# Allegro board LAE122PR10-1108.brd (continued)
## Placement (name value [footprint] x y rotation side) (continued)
RV14  -  [R_0402]  18.77 86.05 180 top
RV15  -  [R_0402]  18.77 86.94 180 top
RV16  -  [R_0402]  18.77 84.21 180 top
RV17  -  [R_0402]  18.77 85.1 180 top
RV18  -  [R_0402]  18.49 77.04 0 top
RV19  -  [R_0402]  20.46 91.39 0 bottom
RV20  -  [R_0402]  23.6 91.39 180 bottom
RV21  -  [R_0402]  24.03 88.67 270 bottom
RV22  -  [R_0402]  16.79 89.85 90 top
RV23  -  [R_0402]  16.79 88.99 270 top
RV26  -  [R_0402]  16.72 81.43 270 bottom
RV29  -  [R_0402]  16.72 83.27 270 bottom
RV32  -  [R_0402]  16.72 86.96 270 bottom
RV35  -  [R_0402]  16.72 85.11 270 bottom
RV70  -  [R_0402]  106.2 131.25 90 top
RV71  -  [R_0402]  107.08 129.31 270 top
RV73  -  [R_0402]  110.5 132.22 0 top
RV74  -  [R_0402]  113.26 132.22 180 top
RV76  -  [R_0402]  107.08 131.25 90 top
RV77  -  [R_0402]  106.2 129.31 270 top
RV79  -  [R_0402]  119.34 131.82 90 bottom
RV80  -  [R_0402]  120.23 131.82 90 bottom
RV81  -  [R_0402]  122.01 131.82 90 bottom
RV82  -  [R_0402]  121.12 131.82 90 bottom
RV83  -  [R_0402]  122.9 131.82 90 bottom
RV84  -  [R_0402]  123.79 131.82 90 bottom
RV85  -  [R_0402]  119.33 128.22 0 bottom
RV87  -  [R_0402]  114.57 126.88 0 top
RV88  -  [R_0402]  114.57 127.77 0 top
RV89  -  [R_0402]  108.35 125.69 270 bottom
RV90  -  [R_0402]  119.33 130.19 0 bottom
RV91  -  [R_0402]  119.33 129.3 0 bottom
RV93  -  [R_0402]  119.33 126.44 0 bottom
RV94  -  [R_0402]  119.33 125.55 0 bottom
RV95  -  [R_0402]  119.33 127.33 0 bottom
RV97  -  [R_0402]  107.28 126.33 270 bottom
RZ8  -  [R_0402]  233.32 55.21 270 top
RZ9  -  [R_0402]  233.32 52.51 90 top
RZ10  -  [R_0402]  222.53 58.57 270 top
RZ18  -  [R_0402]  209.5 58.49 0 top
RZ19  -  [R_0402]  212.19 58.49 180 top
RZ20  -  [R_0402]  214.07 54.94 0 top
RZ21  -  [R_0402]  216.76 54.94 180 top
RZ22  -  [R_0402]  210.46 57.11 270 top
RZ23  -  [R_0402]  211.35 57.11 270 top
RZ25  -  [R_0402]  285.66 12.58 180 bottom
RZ26  -  [R0402_0OHM]  214.97 55.81 90 top
RZ28  -  [R_0402]  287.55 10.69 270 bottom
RZ29  -  [R0402_0OHM]  215.86 55.81 90 top
RZ32  -  [R_0402]  269.71 83.5 90 top
RZ38  -  [R_0402]  251.17 104.01 90 top
RZ40  -  [R_0402]  280.69 86.93 90 top
RZ43  -  [R_0402]  239.5 111.83 180 top
RZ56  -  [R0402_0OHM]  238.03 67.89 180 top
RZ58  -  [R_0402]  160.23 104.72 90 top
RZ59  -  [R_0402]  160.17 101.09 90 top
RZ60  -  [R_0402]  159.08 104.68 90 bottom
RZ61  -  [R0402_0OHM]  158.08 104.7 90 bottom
RZ62  -  [R_0402]  155.13 109.37 180 bottom
RZ63  -  [R_0402]  159.99 104.68 90 bottom
RZ64  -  [R0402_0OHM]  160.11 60.86 270 top
RZ65  -  [R_0402]  161 60.86 270 top
RZ69  -  [R_0402]  161.94 104.68 90 bottom
RZ70  -  [R0402_0OHM]  252.63 107.19 90 top
RZ71  -  [R_0402]  251.74 107.19 90 top
RZ76  -  [R_0402]  240.7 102.2 180 top
RZ77  -  [R_0402]  240.7 101.31 180 top
RZ78  -  [R_0402]  237.12 67 0 top
RZ79  -  [R_0402]  237.12 66.11 0 top
RZ80  -  [R_0402]  237.12 65.23 0 top
RZ81  -  [R_0402]  237.12 64.34 0 top
RZ85  -  [R0402_0OHM]  223.53 52.84 0 top
RZ87  -  [R0402_0OHM]  221.64 58.57 270 top
RZ89  -  [R0402_0OHM]  160.56 115.7 0 bottom
RZ111  -  [R_0402]  159.69 114.27 90 bottom
RZ112  -  [R_0402]  154.21 110.25 0 bottom
RZ113  -  [R_0402]  157.17 105.61 270 bottom
RZ114  -  [R_0402]  223.47 58.57 270 top
RZ116  -  [R_0402]  214.08 55.81 90 top
RZ117  -  [R_0402]  216.75 55.81 90 top
RZ119  -  [R_0402]  134.64 68.39 90 top
RZ120  -  [R0402_0OHM]  140.18 66.3 180 top
RZ128  -  [R_0201]  233.51 84.59 270 bottom
RZ129  -  [R_0201]  234.17 84.59 270 bottom
RZ130  -  [R_0201]  234.83 84.59 270 bottom
RZ131  -  [R_0402]  238.62 98.94 270 top
RZ132  -  [R_0402]  237.74 98.94 270 top
RZ151  -  [R_0603]  121.44 121.61 0 top
RZ320  -  [R_0402]  123.8 128.47 180 bottom
RZ326  -  [R_0402]  231.05 106.06 180 top
RZ334  -  [R_0402]  277.65 57.58 90 bottom
RZ335  -  [R_0402]  277.63 55.75 90 bottom
RZ345  -  [R0402_0OHM]  203.99 52.28 270 top
RZ346  -  [R0402_0OHM]  213.19 55.81 90 top
RZ347  -  [R0402_0OHM]  216.76 57.61 180 top
RZ361  -  [R_0402]  241.96 93 180 top
RZ362  -  [R_0402]  154.21 111.14 0 bottom
RZ363  -  [R0402_0OHM]  158.82 115.19 270 bottom
SW1  -  [SW_SS3-CMFTQR9_3P]  228.24 82.83 65 bottom
SW3  -  [SW_SKRBAAE010_4P]  295.67 126.44 180 top
T1  -  [TPC12]  105.58 109.06 0 top
T2  -  [TPC12]  105.07 111.5 0 top
T3  -  [TPC12]  97.34 84.53 0 top
T4  -  [TPC12]  97.94 85.79 180 bottom
T9  -  [TPC12]  84.24 121.13 180 bottom
T10  -  [TPC12]  101.84 115.5 180 bottom
T11  -  [TPC12]  100.61 116.28 180 bottom
T12  -  [TPC12]  84.73 86.5 180 bottom
T13  -  [TPC12]  87.27 86.5 180 bottom
T14  -  [TPC12]  125.18 98.88 0 top
T15  -  [TPC12]  126.76 98.36 0 top
T16  -  [TPC12]  86 86.5 180 bottom
T17  -  [TPC12]  84.73 87.77 180 bottom
T18  -  [TPC12]  140.04 100.85 180 bottom
T19  -  [TPC12]  131.15 116.6 180 bottom
T50  -  [TPC12]  118.45 51.45 180 bottom
T51  -  [TPC12]  119.85 60.15 0 top
T88  -  [TPC12]  242.59 132.7 0 top
T89  -  [TPC12]  243.1 131.48 0 top
T113  -  [TPC12]  87.27 87.77 180 bottom
T114  -  [TPC12]  86 87.77 180 bottom
T115  -  [TPC12]  125.2 95.13 0 top
T120  -  [TPC12]  128.01 107.39 0 top
T122  -  [TPC12]  114.17 108.47 0 top
T123  -  [TPC12]  114.11 97.96 0 top
T126  -  [TPC12]  135.33 91.01 180 bottom
T127  -  [TPC12]  135.47 89.74 180 bottom
T130  -  [TPC12]  136.82 88.91 180 bottom
T132  -  [TPC12]  93.6 91.98 0 top
T219  -  [TPC12]  28.66 87.83 180 bottom
T220  -  [TPC12]  27.01 84.4 270 bottom
T225  -  [TPC12]  230.94 95.26 0 top
T226  -  [TPC12]  94.31 90.79 0 top
T258  -  [TPC12]  134.75 87.39 180 bottom
T262  -  [TPC12]  250.06 96.58 0 top
T264  -  [TPC12]  250.52 95.39 0 top
T267  -  [TPC12]  271.8 92.21 0 top
T268  -  [TPC12]  135.94 87.95 180 bottom
T281  -  [TPC12]  102.42 120.75 180 bottom
T282  -  [TPC12]  103.86 120.72 180 bottom
T283  -  [TPC12]  163.16 109.92 180 bottom
TL1  -  [MHPC_NS692417_24P]  258.72 128.94 0 bottom
UA1  -  [ALC3246-CG_MQFN48_6X6]  259.53 63.39 270 top
UC1  -  [SKL-U_BGA_1356P-T]  132.41 113.31 0 bottom
UC5  -  [W25Q128FVSIQ_SO8]  160.68 95.32 270 bottom
UC6  -  [W25Q128FVSIQ_SO8]  160.68 101.23 270 bottom
UC7  -  [TC7SH08FU_SSOP5]  156.68 119.79 270 bottom
UC8  -  [74CBTLV3126BQ_DHVQFN14_2P5X3-S]  82.78 122.3 180 bottom
UC12  -  [74AHC1G09GW_TSSOP5]  151.29 115.98 270 bottom
UD1  -  [74AUP1G07GW_TSSOP5]  72.36 84.16 270 bottom
UE1  -  [MEC5105_WFBGA_169P]  246.68 83.86 90 top
UE2  -  [IT8010FN-BX-R_QFN20_4X4]  267.25 90.67 90 top
UE3  -  [TC7SH08FU_SSOP5]  266.6 98.9 270 top
UE4  -  [74AUP1G07GW_TSSOP5]  269.88 96.78 0 top
UE5  -  [TC7SH08FU_SSOP5]  263.23 98.96 270 top
UE6  -  [74AUP1G07GW_TSSOP5]  266.65 80.73 270 top
UE7  -  [AP2112K-3P3TRG1_SOT23-5]  241.85 98.56 270 top
UE9  -  [W25Q80DVSSIG_SO8]  249.84 123.07 270 bottom
UI1  -  [SY6288D20AAC_SOT23-5]  20.02 55.71 0 bottom
UI3  -  [SLGC55544CVTR_TQFN16_3X3]  277.51 77.32 180 top
UL1  -  [WGI217LM-QPN9-A2_QFN48_6X6-S]  244.08 122.96 0 top
UL2  -  [TC7SH08FU_SSOP5]  254.97 132.74 270 bottom
UR1  -  [RTS5242-GR_QFN32_4X4-S]  273.22 66.27 0 top
UT5  -  [TPS65982_BGA_96P]  34.02 83.47 270 top
UT6  -  [W25Q80DVSSIG_SO8]  25.04 68.59 90 bottom
UT7  -  [AP2112K-3P3TRG1_SOT23-5]  19.97 67.56 0 bottom
UT8  -  [AP2204R-5P0TRG1_SOT89-3]  16.91 75.49 270 bottom
UT9  -  [TUSB546_QFN40_4X6]  26.37 100.85 90 top
UV2  -  [AP2330W-7_SC59-3]  19.26 90.87 180 bottom
UV7  -  [PS8338BQFN60GTR-A0_QFN60_5X9-S]  117.11 127.25 180 bottom
UV24  -  [G524B1T11U_SOT23-5]  66.8 125.27 180 top
UZ2  -  [TPS22966DPUR_SON14_2X3]  252.32 110 90 top
UZ3  -  [TPS22966DPUR_SON14_2X3]  158.59 59.14 90 top
UZ4  -  [TPS22966DPUR_SON14_2X3]  279.19 89.74 90 top
UZ5  -  [TPS22966DPUR_SON14_2X3]  245.38 65.03 270 top
UZ6  -  [TC7SH08FU_SSOP5]  203.1 59.72 270 top
UZ8  -  [AOZ1336_DFN8_2X2]  206.38 52.39 270 top
UZ10  -  [TC7SH08FU_SSOP5]  268.56 84.83 90 top
UZ12  -  [NPCT650JB2YX_QFN32_5X5]  157.33 112.52 270 bottom
UZ19  -  [TPS22961DNYR_WSON8]  123.74 128.49 180 top
UZ21  -  [TPS22961DNYR_WSON8]  128.13 128.49 180 top
UZ26  -  [TPS22961DNYR_WSON8]  135.89 66.61 0 top
UZ34  -  [TC7SH08FU_SSOP5]  140.44 69.6 180 top
UZ35  -  [TC7SH08FU_SSOP5]  124.35 130.77 270 bottom
YC1  -  [Y_X3G024000DC1H_4P]  112.84 122.04 0 bottom
YC2  -  [Y_9H03200042_2P]  134.81 80.15 180 top
YE1  -  [Y_X1A000141000200_2P]  242.02 82.2 90 top
YL1  -  [Y_7V25000034_4P]  248.9 118.13 180 top

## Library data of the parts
CA1-CA6 CA12 CA13 CA19 CA22-CA24 CA27 CA28 CA33 CA35 CA41 CA54 CA62-CA69 CA72 CC7 CC8 CC21-CC27 CC32 CC33 CC176-CC179 CC195 CC199 CC202-CC209 CC211-CC213 CC215-CC218 CC222 CC224 CC250-CC253 CC264-CC266 CC269 CC288 CC297 CC300-CC308 CC310 CC312 CC316 CC318-CC326 CC331-CC333 CD9-CD16 CD18 CD19 CD23-CD27 CD29 CD31 CE1-CE6 CE8 CE10 CE12 CE14 CE24 CE26-CE31 CE35-CE40 CE46 CE47 CE52-CE54 CE57 CE59-CE62 CE500 CE503 CI4 CI5 CI13 CI16 CI29-CI31 CI43-CI46 CL1 CL2 CL5 CL6 CL13 CL14 CL18 CL29 CL30 CN60 CN69-CN72 CR1 CR4 CR11-CR15 CR21 CR22 CR25-CR28 CT70-CT74 CT83 CT85-CT87 CT89 CT90 CT92 CT93 CT103-CT117 CT122 CT189 CV1-CV6 CV13 CV14 CV17-CV25 CV31-CV38 CV81 CV82 CV96 CV145-CV150 CV152 CV153 CV156 CV157 CZ3 CZ10-CZ15 CZ17-CZ19 CZ21 CZ23-CZ25 CZ28 CZ29 CZ33-CZ41 CZ56-CZ63 CZ69 CZ71-CZ73 CZ75 CZ80 CZ81 CZ83 CZ100 CZ102 CZ104 CZ105 CZ109 CZ110 CZ113 CZ114 CZ117 CZ118 CZ121 CZ124 CZ126 CZ127 CZ197 CZ198 PC1 PC2 PC9 PC10 PC100 PC103 PC113 PC115 PC116 PC127 PC128 PC202 PC203 PC206-PC208 PC216-PC218 PC221 PC222 PC301 PC303 PC307 PC401 PC402 PC408-PC411 PC417-PC420 PC503 PC505 PC506 PC513 PC515 PC601 PC602 PC605 PC613 PC614 PC616-PC621 PC624-PC633 PC636 PC637 PC639-PC647 PC649-PC654 PC659-PC661 PC677 PC679 PC680 PC685 PC686 PC688 PC902 PC903 PC925-PC929 PC932 PC933 PC937-PC939 PC942-PC947 PC949 PC950 PC1201 PC1203-PC1208 PC1210-PC1214 PC1216 PC1217 PC1286 = C_0402
CA7 CA8 CA10 CA45 CA47 CA55 CA57 CA60 CC9 CC10 CC28-CC30 CC214 CC223 CC270 CC281 CC313 CC314 CD28 CD32 CE11 CE13 CE15 CE18-CE23 CE25 CI3 CI7 CI17 CI19 CL3 CL7-CL11 CL15-CL17 CL19-CL21 CN61 CN62 CR2 CR3 CR6 CR7 CR17 CR19 CT80 CT81 CT88 CT95-CT102 CT118-CT121 CV12 CV39 CV40 CV83-CV95 CZ1 CZ2 CZ30 CZ31 CZ50 CZ51 CZ53 CZ54 CZ64 CZ66-CZ68 CZ82 CZ90-CZ93 CZ101 CZ103 CZ106 CZ111 CZ112 CZ115 CZ116 CZ119 CZ120 CZ122 CZ125 CZ128 PC1030-PC1056 PC1083-PC1099 PC1125 PC1126 PC1147-PC1153 PC1164 = C_0201
CA9 CA25 CA29 CA31 CA43 CA44 CA46 CA48 CA49 CA51-CA53 CA56 CA58 CA59 CA61 CC279 CC280 CC294-CC296 CD1-CD8 CD20-CD22 CE16 CE17 CE32 CI6 CI33 CI34 CL4 CL12 CN63 CN64 CR5 CR18 CR20 CT82 CT84 CT91 CT94 CV11 CV15 CV16 CV41 CZ20 CZ27 CZ32 CZ52 CZ55 PC3-PC7 PC11 PC102 PC111 PC112 PC114 PC119 PC125 PC126 PC204 PC205 PC209-PC214 PC219 PC302 PC304-PC306 PC308-PC313 PC403 PC404 PC406 PC407 PC412 PC413 PC415 PC416 PC422 PC424 PC501 PC502 PC504 PC514 PC516 PC603 PC604 PC611 PC622 PC655 PC662 PC671 PC678 PC930 PC931 PC934 PC940 PC941 PC1001-PC1029 PC1057-PC1061 PC1064-PC1082 PC1129-PC1146 PC1170-PC1181 PC1202 = C_0603
CC210 CC219-CC221 CC225 CC226 CL28 CT75-CT78 PC8 PC104-PC110 PC117 PC118 PC120-PC124 PC129 PC130 PC200 PC201 PC608 PC612 PC656-PC658 PC663-PC665 PC672 PC673 PC904-PC906 PC911 PC913-PC920 PC935 PC936 = C_0805
CD17 PC1062 PC1063 = C_D3
CI1 CI14 = C_1206
CI32 CZ26 PC909 PC910 PC951 = C_B2
CL22 = C_1808
CMOS1 = SHORTPADS-NPM: User Part Number: PART#
DA1-DA3 DA6 DA7 = L03ESDL5V0CC3-2_SOT23-3
DA8 DE1 DZ1 DZ2 DZ5-DZ7 = RB751S40T1G_SOD523-2
DI1 DI4 = L05ESDL5V0NA-4_SLP2510P8-10-9
DI2 DI5 DV4 = AZC199-02SPR7G_SOT23-3
DT1-DT3 = 1N4148WS-7-F_SOD323-2
DT4 = L30ESD24VC3-2_SOT23-3
DT5-DT20 DV7 DV8 = ESD8011MUT5G_X3DFN2-2-S
DV1-DV3 PD905 PD1801 = BAT54CW_SOT323-3
FD1-FD4 = FIDUCIAL_C40M80
H1-H4 = H_3P4
H5 H6 = H_1P0N
H7 H8 H25 H26 = H_3P2
H9 H14-H16 H18 H23 H24 H29 H33 H38 = H_2P6-G
H10 = H_3P8-G
H12 H21 H22 H27 H28 = H_3P5-G
H20 H37 = H_3P1-G
H30 = H_2P3X2P7N
H39 = H_2P3N
JAPS1 = CVILU_CF4218FH0R0-05-NH_18P-T
JDB1 = ACES_50506-00641-P01_6P
JDEG1 = HB_A531015-SCHR21_10P
JDIMM1 = LCN_DAN05-Q0406-0103_260P
JEDP1 = ACES_50398-04041-001_40P
JESPI = ACES_50506-01041-P01_10P
JFAN1 = ACES_50271-0040N-001_4P
JHDMI1 = ACON_HMRBL-A41L0F_19P-T
JHP1 = SINGA_2SJ3095-085111F_6P
JIR1 = E-T_4251K-F06N-40L_6P
JKBTP1 = CVILU_CF5020FD0RK-05-NH_20P-T
JLED1 = ACES_50209-0060N-P01_6P
JLOM1 = SANTA_130470-19_13P-T
JNGFF1 = LCN_DAN05-67306-0100_75P
JNGFF2 = BELLW_80149-3221_67P
JNGFF3 = LOTES_APCI0170-P001A_75P
JRTC1 = ACES_50271-0020N-001_2P
JSD1 = T-SOL_158-1240902600_23P-T
JSIM1 = JAE_SF51S006V4DR1000Q_8P
JSPI1 = E-T_6705K-Y20N-00L_20P
JSPK1 = ACES_50278-0040N-001_4P
JTAG1 = SHORTPADS: User Part Number: PART#
JUART1 = CVILU_CI1804M1VRA-NH_4P
JUSB1 JUSB2 = ACON_TCRA2-9U1U93_9P-T
JUSBC1 = JAE_DX07B024XJ1R1300_24P
JUSH1 = CVILU_CF5026FD0RK-05-NH_26P-T
JXDP1 = E-T_6601K-Y61N-04L_61P
LA5 LA12 LA14 LT11 LT13 = MURAT_BLM15PX600SN1D_2P
LA6-LA11 = MURAT_BLM15PX330SN1D_2P
LA13 = TAI-T_HCB2012VF-601T20_2P
LC1 LC2 = MURAT_BLM15GA750SN1D_2P
LED3 = LED_LTW-C193DC-C_2P
LI3 LI7 LV27 LZ1 = PANAS_EXC24CQ900U_4P
LI8 LI9 LI16 LI17 = INPAQ_HCM2012GA900AE_4P
LL1 = TAIYO_BRC2012T4R7MD_2P
LV1 = MURAT_BLM15PX221SN1D_2P
LV3 LV6 LV9 LV12 = TAIYO_MCF12102G900-T_4P
LV31-LV38 = MURAT_LQG15HN12NJ02D_2P
PBATT1 = DEREN_40-42251-01001RHF_10P-T
PC606 = C_D
PC1127 PC1128 = C_D2
PD1 PD2 = TVNST52302AB0_SOT523-3
PD3 = DB3J315E0L_SMINI3-F2-B3
PD4 = PESD5V0U2BT_SOT23-3
PD5 PD1202 = PDS5100H-13_POWERDI5-3
PD100 PD903 = RB520SM-30T2R_EMD2-2
PD901 PD904 PD1205 = SDMK0340L-7-F_SOD323-2
PH601-PH605 PR1-PR8 PR10-PR12 PR14-PR18 PR24 PR27 PR28 PR102 PR103 PR107 PR108 PR113 PR116 PR117 PR204-PR207 PR209 PR212 PR302 PR306-PR308 PR310 PR311 PR403 PR404 PR407 PR408 PR410-PR422 PR424 PR427 PR428 PR501 PR505 PR506 PR514-PR517 PR601 PR604 PR605 PR608 PR610-PR613 PR617 PR618 PR621-PR623 PR626 PR628-PR633 PR635 PR636 PR638-PR652 PR656 PR657 PR662 PR678 PR680 PR909 PR910 PR915 PR918 PR919 PR925 PR927 PR930-PR934 PR937 PR938 PR940 PR944 PR945 PR948 PR950 PR953 PR1201-PR1203 PR1205-PR1210 PR1212-PR1214 PR1217 PR1219 PR1222 PR1224 PR1226-PR1237 PR1239 PR1240 PR1246-PR1249 PR1251-PR1255 PR1258-PR1261 RA5-RA9 RA12-RA14 RA17 RA18 RA44 RA45 RA50-RA53 RA57-RA61 RC1-RC7 RC10-RC17 RC19-RC23 RC25 RC27-RC32 RC39 RC42-RC48 RC50-RC52 RC54 RC56 RC57 RC59 RC60 RC65 RC67-RC69 RC71-RC75 RC77-RC84 RC86-RC96 RC109 RC110 RC112-RC115 RC120-RC124 RC126 RC128-RC141 RC152 RC153 RC157 RC161 RC163 RC165-RC168 RC175-RC178 RC183 RC184 RC186 RC187 RC189 RC190 RC211 RC215 RC217-RC220 RC222-RC225 RC227 RC234 RC237 RC239-RC241 RC243 RC267 RC268 RC272 RC278 RC279 RC282 RC283 RC287 RC288 RC291 RC292 RC297 RC298 RC311 RC313 RC316-RC319 RC323 RC324 RC330 RC331 RC338 RC344-RC349 RC362 RC363 RC366-RC369 RC371 RC372 RC387 RC400-RC403 RC405 RC407-RC411 RC413 RC414 RD4 RD6 RD8 RD11 RD14-RD19 RE5 RE6 RE8 RE10-RE18 RE20 RE21 RE25 RE26 RE31 RE33 RE35 RE37 RE38 RE43 RE48 RE51 RE55-RE58 RE60 RE63-RE65 RE67-RE75 RE77 RE79 RE83-RE86 RE91 RE92 RE94 RE95 RE98 RE274 RE280 RE288 RE292 RE300-RE304 RE306 RE308 RE312-RE314 RE324 RE337-RE343 RE348-RE350 RE361-RE363 RE365-RE377 RE505 RE507 RE508 RE512-RE514 RE524-RE526 RE530 RE532 RE536 RE537 RE539 RI13 RI14 RI27-RI30 RI47-RI50 RL1 RL2 RL4-RL6 RL9 RL11-RL20 RL29 RL30 RL70 RN37 RN100 RN101 RR3 RR4 RR19 RT50-RT53 RT64-RT68 RT71 RT74-RT76 RT81 RT82 RT84-RT88 RT95-RT98 RT100 RT101 RT103 RT106 RT107 RT110 RT111 RT130-RT133 RT135-RT145 RT247 RT248 RT300-RT308 RT339 RT375-RT379 RT393 RV1-RV8 RV10-RV23 RV26 RV29 RV32 RV35 RV70 RV71 RV73 RV74 RV76 RV77 RV79-RV85 RV87-RV91 RV93-RV95 RV97 RZ8-RZ10 RZ18-RZ23 RZ25 RZ28 RZ32 RZ38 RZ40 RZ43 RZ58-RZ60 RZ62 RZ63 RZ65 RZ69 RZ71 RZ76-RZ81 RZ111-RZ114 RZ116 RZ117 RZ119 RZ131 RZ132 RZ320 RZ326 RZ334 RZ335 RZ361 RZ362 = R_0402
PJP1 PJP2 PJP4 PJP7 PJP13 PJP15 PJP16 PJP18-PJP22 PJP35 PJP37 PJP38 PJP42 PJP201 PJP391 PJP403 PJP404 PJP501 PJP502 PJP505 PJP506 PJP603 = JUMP_43X39
PJP3 PJP8 PJP31 PJP39 PJP41 PJP102 PJP103 PJP200 PJP302 PJP601 PJP1202 = JUMP_43X118
PJP14 PJP17 PJP36 PJP40 PJP100 PJP101 PJP202 PJP301 PJP401 PJP402 PJP602 = JUMP_43X79
PJP901 = JUMP_43X118-NPM
PJPDC1 = CVILU_CI0805M1HRC-NH_5P-T
PL1 PL2 PL4 = TAIYO_FBMJ4516HS720NT_2P
PL3 = MURAT_BLM15AG102SN1D_2P
PL100 PL101 = CYNTE_PCMC063T-1R5MN_2P
PL201 = CYNTE_PCMB063T-1R0MS_2P
PL301 = MAG_MMD-05CZ-R68M-X2L_2P
PL402 PL404 PL501 = MAG_MLV-FY12N1R0M-O1L_2P
PL602 = 9A_Z80_1812_2P-NPM
PL610 PL612 = MAG_MMD06CZER15MG_4P
PL614 = MAG_MMD05CZR47M_4P
PL901 = MAGLA_MMD-05CZ-1R0M-M7L_2P
PL902 = CYNTE_PCMB103T-2R2MS_2P
PL1201 PL1202 = 5A_Z120_0805_2P
PQ1 PQ1201 PQ1204 PQ1209 PQ1214 QC2 QE2 QE13 QL1 QL2 QV3 QZ2 QZ7 = DMN65D8LDW-7_SOT363-6
PQ2 = FDV301N-G_SOT23-3
PQ3 = MMST3904-7-F_SOT323-3
PQ4 PQ9 PQ1202 PQ1206 PQ1213 = FDMC6679AZ_MLP8-5
PQ5 PQ1203 PQ1215 = NTR4502PT1G_SOT23-3
PQ6-PQ8 PQ909 PQ1205 PQ1212 PQ1216 = DMN65D8LW-7_SOT323-3
PQ501 = AON7934_DFN3X3A8-10
PQ904 = AON6970_DFN5X6D-8-7
PQ905 = AON6992_DFN5X6D-8-7
PQ906 = AON7409_DFN8-5
PQ1207 PQ1208 PQ1210 PQ1211 QT1 = DMN66D0LDW-7_SOT363-6
PR13 PR916 = R_0805
PR19-PR23 PR25 PR26 PR29 PR104 PR105 PR114 PR119 PR120 PR208 PR210 PR312 PR402 PR406 PR423 PR425 PR426 PR504 PR513 PR602 PR603 PR606 PR614 PR616 PR620 PR625 PR659 PR671 PR679 PR920 PR922 PR926 PR928 PR929 PR935 PR936 PR939 PR941 PR942 PR946 PR947 PR949 PR951 PR960 PR1211 PR1215 PR1216 PR1218 PR1220 PR1221 PR1223 PR1225 PR1238 PR1241-PR1245 PR1250 PR1257 RA35-RA39 RA48 RA54-RA56 RC33-RC38 RC40 RC41 RC62 RC170 RC171 RC173 RC212 RC214 RC221 RC228-RC231 RC235 RC244 RC290 RC295 RC296 RC300-RC308 RC325 RC328 RC337 RC373-RC377 RD5 RD7 RD9 RD12 RE30 RE32 RE34 RE59 RE90 RE275 RE290 RE318 RE360 RE364 RE515 RL3 RL7 RL34 RN99 RR5-RR10 RT54-RT60 RT63 RT69 RT70 RT72 RT73 RT83 RT89 RT90 RT92 RT93 RT99 RT104 RT105 RT108 RT109 RT120-RT123 RT246 RT380 RZ26 RZ29 RZ56 RZ61 RZ64 RZ70 RZ85 RZ87 RZ89 RZ120 RZ345-RZ347 RZ363 = R0402_0OHM
PR100 PR111 PR203 PR304 PR914 PR943 R274 RA3 RC143 RC169 RC216 RC299 RC309 RC310 RD10 RL8 = R0603_0OHM
PR106 PR112 PR202 PR303 PR627 PR663 PR676 PR923 PR924 = R_1206
PR405 PR409 PR502 PR619 PR624 PR660 PR661 PR672 PR674 PR921 RL71-RL78 RZ151 = R_0603
PR901 PR917 = R_1206_4P-D
PRP1 RPC1 RPC3 RPC4 RPE7 RPE9-RPE12 = RP_0804_8P4R
PT1 T1-T4 T9-T19 T50 T51 T88 T89 T113-T115 T120 T122 T123 T126 T127 T130 T132 T219 T220 T225 T226 T258 T262 T264 T267 T268 T281-T283 = TPC12
PU1 PU903 PU1200 UC7 UE3 UE5 UL2 UZ6 UZ10 UZ34 UZ35 = TC7SH08FU_SSOP5
PU2 = AP2204RA-3P3TRG1_SOT89-3
PU100 = SY8288BRAC_QFN20_3X3
PU102 = SY8288CRAC_QFN20_3X3
PU200 = SY8210AQVC_QFN19_4X3
PU301 = SYX196DQNC_QFN10_3X3
PU401 PU402 = SY8057QDC_QFN16_3X3
PU501 = RT8097ALGE_SOT23-6
PU503 = AP7361C-FGE-7_U-DFN3030-8_3X3
PU602 = ISL62883CHRTZ-T_TQFN40_5X5-S
PU610 PU612 = CSD97374CQ4M_SON8_3P5X4P5
PU614 = ISL95808HRZ-TS2378_DFN8_2X2-S
PU901 = ISL88738HRTZ-T_TQFN32_4X4
PU1201 = LM393DGKR_VSSOP8
QE3-QE7 = MMBT3904WT1G_SC70-3
QE11 QE12 QR1 QV2 QV4 QV5 QV7 = L2N7002WT1G_SC-70-3
QV1 = AO6405_TSOP6
QV8 QZ1 QZ9 = LP2301ALT1G_SOT23-3
QZ3 = DDTA114EUA-7-F_SOT323-3
RE93 RZ128-RZ130 = R_0201
SW1 = SW_SS3-CMFTQR9_3P
SW3 = SW_SKRBAAE010_4P
TL1 = MHPC_NS692417_24P
UA1 = ALC3246-CG_MQFN48_6X6
UC1 = SKL-U_BGA_1356P-T
UC5 UC6 = W25Q128FVSIQ_SO8
UC8 = 74CBTLV3126BQ_DHVQFN14_2P5X3-S
UC12 = 74AHC1G09GW_TSSOP5
UD1 UE4 UE6 = 74AUP1G07GW_TSSOP5
UE1 = MEC5105_WFBGA_169P
UE2 = IT8010FN-BX-R_QFN20_4X4
UE7 UT7 = AP2112K-3P3TRG1_SOT23-5
UE9 UT6 = W25Q80DVSSIG_SO8
UI1 = SY6288D20AAC_SOT23-5
UI3 = SLGC55544CVTR_TQFN16_3X3
UL1 = WGI217LM-QPN9-A2_QFN48_6X6-S
UR1 = RTS5242-GR_QFN32_4X4-S
UT5 = TPS65982_BGA_96P
UT8 = AP2204R-5P0TRG1_SOT89-3
UT9 = TUSB546_QFN40_4X6
UV2 = AP2330W-7_SC59-3
UV7 = PS8338BQFN60GTR-A0_QFN60_5X9-S
UV24 = G524B1T11U_SOT23-5
UZ2-UZ5 = TPS22966DPUR_SON14_2X3
UZ8 = AOZ1336_DFN8_2X2
UZ12 = NPCT650JB2YX_QFN32_5X5
UZ19 UZ21 UZ26 = TPS22961DNYR_WSON8
YC1 = Y_X3G024000DC1H_4P
YC2 = Y_9H03200042_2P
YE1 = Y_X1A000141000200_2P
YL1 = Y_7V25000034_4P

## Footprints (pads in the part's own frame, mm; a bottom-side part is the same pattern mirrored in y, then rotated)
1N4148WS-7-F_SOD323-2
  rect 1.346x0.66 smd: 1(0,0) 2(2.4,0)
5A_Z120_0805_2P
  rect 0.991x0.991 smd: 1(0,0) 2(2,0)
9A_Z80_1812_2P-NPM
  rect 1.803x3.404 smd: 1(0,0) 2(3.8,0)
74AHC1G09GW_TSSOP5
  oval 0.381x1.346 smd: 1(0,0) 2(0.65,0) 3(1.3,0) 4(1.3,1.79) 5(0,1.79)
74AUP1G07GW_TSSOP5
  oval 0.381x1.346 smd: 1(0,0) 2(0.65,0) 3(1.3,0) 4(1.3,1.79) 5(0,1.79)
74CBTLV3126BQ_DHVQFN14_2P5X3-S
  oval 1.041x0.254 smd: 1(0,0) 7(2.95,0) 8(2.95,0.5) 14(0,0.5)
  oval 0.254x1.041 smd: 2(0.475,-0.975) 3(0.975,-0.975) 4(1.475,-0.975) 5(1.975,-0.975) 6(2.475,-0.975) 9(2.475,1.475) 10(1.975,1.475) 11(1.475,1.475) 12(0.975,1.475) 13(0.475,1.475)
  rect 1.499x0.991 smd: 15(1.475,0.25)
ACES_50209-0060N-P01_6P
  oval 0.508x1.651 smd: 1(0,0) 2(0.8,0) 3(1.6,0) 4(2.4,0) 5(3.2,0) 6(4,0)
  rect 1.194x1.702 smd: 7(-1.3,-2.275) 8(5.3,-2.275)
ACES_50271-0020N-001_2P
  oval 0.787x1.6 smd: 1(0,0) 2(1.25,0)
  rect 2.108x2.997 smd: 3(3.8,-2.9) 4(-2.55,-2.9)
ACES_50271-0040N-001_4P
  oval 0.787x1.6 smd: 1(0,0) 2(-1.25,0) 3(-2.5,0) 4(-3.75,0)
  rect 2.108x2.997 smd: 5(2.55,-2.9) 6(-6.3,-2.9)
ACES_50278-0040N-001_4P
  oval 0.787x1.905 smd: 1(0,0) 2(1.25,0) 3(2.5,0) 4(3.75,0)
  rect 1.295x3.353 smd: 5(-2.85,-4.925) 6(6.6,-4.925)
ACES_50398-04041-001_40P
  oval 0.254x1.295 smd: 1(0,0) 2(0.5,0) 3(1,0) 4(1.5,0) 5(2,0) 6(2.5,0) 7(3,0) 8(3.5,0) 9(4,0) 10(4.5,0) 11(5,0) 12(5.5,0) 13(6,0) 14(6.5,0) 15(7,0) 16(7.5,0) 17(8,0) 18(8.5,0) 19(9,0) 20(9.5,0) 21(10,0) 22(10.5,0) 23(11,0) 24(11.5,0) 25(12,0) 26(12.5,0) 27(13,0) 28(13.5,0) 29(14,0) 30(14.5,0) 31(15,0) 32(15.5,0) 33(16,0) 34(16.5,0) 35(17,0) 36(17.5,0) 37(18,0) 38(18.5,0) 39(19,0) 40(19.5,0)
  rect 1.194x3.2 smd: 41(-2.4,1.95) 45(21.9,1.95)
  rect 2.311x1.295 smd: 42(0.85,3.9) 43(9.75,3.9) 44(18.65,3.9)
ACES_50506-00641-P01_6P
  oval 0.305x0.889 smd: 1(0,0) 2(0.5,0) 3(1,0) 4(1.5,0) 5(2,0) 6(2.5,0)
  rect 0.991x2.007 smd: 7(-2.1,-3.05) 8(4.6,-3.05)
ACES_50506-01041-P01_10P
  oval 0.305x0.889 smd: 1(0,0) 2(0.5,0) 3(1,0) 4(1.5,0) 5(2,0) 6(2.5,0) 7(3,0) 8(3.5,0) 9(4,0) 10(4.5,0)
  rect 0.991x2.007 smd: 11(-2.1,-3.05) 12(6.6,-3.05)
ACON_HMRBL-A41L0F_19P-T
  round 0.813 hole 0.559: 1(0,0) 2(0.5,1.55) 3(1,0) 4(1.5,1.55) 5(2,0) 6(2.5,1.55) 7(3,0) 8(3.5,1.55) 9(4,0) 10(4.5,1.55) 11(5,0) 12(5.5,1.55) 13(6,0) 14(6.5,1.55) 15(7,0) 16(7.5,1.55) 17(8,0) 18(8.5,1.55) 19(9,0)
  oval 1.397x2.21 hole 0.787x1.6: 20(11.75,0.2) 22(-2.75,0.2)
  oval 1.702x2.997 hole 1.092x2.388: 21(13.25,-8.15) 23(-4.25,-8.15)
ACON_TCRA2-9U1U93_9P-T
  round 1.295 hole 0.711: 1(0,0) 2(-2.5,0) 3(-4.5,0) 4(-7,0) 5(-7.5,-1.5) 6(-5.5,-1.5) 7(-3.5,-1.5) 8(-1.5,-1.5) 9(0.5,-1.5)
  oval 1.295x2.311 hole 0.711x1.702: 10(2.9,0.3) 12(-9.9,0.3)
  oval 1.295x2.007 hole 0.711x1.397: 11(4.2,-8.95) 13(-11.2,-8.95)
ALC3246-CG_MQFN48_6X6
  oval 0.889x0.203 smd: 1(0,0) 2(0,-0.4) 3(0,-0.8) 4(0,-1.2) 5(0,-1.6) 6(0,-2) 7(0,-2.4) 8(0,-2.8) 9(0,-3.2) 10(0,-3.6) 11(0,-4) 12(0,-4.4) 25(6.1,-4.4) 26(6.1,-4) 27(6.1,-3.6) 28(6.1,-3.2) 29(6.1,-2.8) 30(6.1,-2.4) 31(6.1,-2) 32(6.1,-1.6) 33(6.1,-1.2) 34(6.1,-0.8) 35(6.1,-0.4) 36(6.1,0)
  oval 0.203x0.889 smd: 13(0.85,-5.25) 14(1.25,-5.25) 15(1.65,-5.25) 16(2.05,-5.25) 17(2.45,-5.25) 18(2.85,-5.25) 19(3.25,-5.25) 20(3.65,-5.25) 21(4.05,-5.25) 22(4.45,-5.25) 23(4.85,-5.25) 24(5.25,-5.25) 37(5.25,0.85) 38(4.85,0.85) 39(4.45,0.85) 40(4.05,0.85) 41(3.65,0.85) 42(3.25,0.85) 43(2.85,0.85) 44(2.45,0.85) 45(2.05,0.85) 46(1.65,0.85) 47(1.25,0.85) 48(0.85,0.85)
  rect 4.394x4.394 smd: 49(3.05,-2.2)
AO6405_TSOP6
  oval 0.508x1.473 smd: 1(0,0) 2(0.95,0) 3(1.9,0) 4(1.9,2.35) 5(0.95,2.35) 6(0,2.35)
AON6970_DFN5X6D-8-7
  oval 0.66x0.635 smd: 1(0,0) 3(3.81,5.67) 4(2.54,5.67) 5(1.27,5.67) 6(0,5.67)
  custom 0.485x0.485 smd: 2(1.905,0.655)
  rect 3.988x2.667 smd: 7(1.905,3.62)
AON6992_DFN5X6D-8-7
  oval 0.66x0.635 smd: 1(0,0) 3(3.81,5.67) 4(2.54,5.67) 5(1.27,5.67) 6(0,5.67)
  custom 0.485x0.485 smd: 2(1.905,0.655)
  rect 3.988x2.667 smd: 7(1.905,3.62)
AON7409_DFN8-5
  oval 0.406x0.991 smd: 1(0,0) 2(0.66,0) 3(1.32,0) 4(1.98,0)
  custom 0.559x0.559 smd: 5(0.99,2.247)
AON7934_DFN3X3A8-10
  oval 0.457x0.508 smd: 1(0,0) 2(0.65,0) 3(1.3,0) 4(1.95,0) 5(1.95,2.76) 6(1.3,2.76) 7(0.65,2.76) 8(0,2.76)
  rect 2.54x1.041 smd: 9(0.975,1.813)
  rect 2.54x0.559 smd: 10(0.975,0.708)
AOZ1336_DFN8_2X2
  oval 0.254x0.787 smd: 1(0,0) 2(0.5,0) 3(1,0) 4(1.5,0) 5(1.5,2.2) 6(1,2.2) 7(0.5,2.2) 8(0,2.2)
  rect 1.499x0.889 smd: 9(0.75,1.1)
AP2112K-3P3TRG1_SOT23-5
  oval 0.508x0.965 smd: 1(0,0) 2(0.95,0) 3(1.9,0) 4(1.9,2.375) 5(0,2.375)
AP2204R-5P0TRG1_SOT89-3
  oval 0.889x1.295 smd: 1(0,0) 3(3,0)
  custom 0.433x0.433 smd: 2(1.5,1.775)
AP2204RA-3P3TRG1_SOT89-3
  oval 0.889x1.295 smd: 1(0,0) 3(3,0)
  custom 0.433x0.433 smd: 2(1.5,1.775)
AP2330W-7_SC59-3
  oval 0.787x0.991 smd: 1(0,0) 2(-0.95,-2.4) 3(0.95,-2.4)
AP7361C-FGE-7_U-DFN3030-8_3X3
  oval 0.457x0.94 smd: 1(0,0) 2(0.65,0) 3(1.3,0) 4(1.95,0) 5(1.95,3.05) 6(1.3,3.05) 7(0.65,3.05) 8(0,3.05)
  rect 2.261x1.499 smd: 9(0.975,1.525)
AZC199-02SPR7G_SOT23-3
  oval 1.016x1.524 smd: 1(0,0) 2(0.965,2.083) 3(-0.965,2.083)
BAT54CW_SOT323-3
  oval 0.711x0.889 smd: 1(0,0) 2(-0.65,-1.9) 3(0.65,-1.9)
BELLW_80149-3221_67P
  round 1.092 hole 1.092 unplated: (-0.75,-5.275)
  round 1.6 hole 1.6 unplated: (19.25,-5.275)
  oval 0.305x1.549 smd: 1(0,0) 2(0.25,-7.55) 3(0.5,0) 4(0.75,-7.55) 5(1,0) 6(1.25,-7.55) 7(1.5,0) 8(1.75,-7.55) 9(2,0) 10(2.25,-7.55) 11(2.5,0) 12(4.75,-7.55) 13(5,0) 14(5.25,-7.55) 15(5.5,0) 16(5.75,-7.55) 17(6,0) 18(6.25,-7.55) 19(6.5,0) 20(6.75,-7.55) 21(7,0) 22(7.25,-7.55) 23(7.5,0) 24(7.75,-7.55) 25(8,0) 26(8.25,-7.55) 27(8.5,0) 28(8.75,-7.55) 29(9,0) 30(9.25,-7.55) 31(9.5,0) 32(9.75,-7.55) 33(10,0) 34(10.25,-7.55) 35(10.5,0) 36(10.75,-7.55) 37(11,0) 38(11.25,-7.55) 39(11.5,0) 40(11.75,-7.55) 41(12,0) 42(12.25,-7.55) 43(12.5,0) 44(12.75,-7.55) 45(13,0) 46(13.25,-7.55) 47(13.5,0) 48(13.75,-7.55) 49(14,0) 50(14.25,-7.55) 51(14.5,0) 52(14.75,-7.55) 53(15,0) 54(15.25,-7.55) 55(15.5,0) 56(15.75,-7.55) 57(16,0) 58(16.25,-7.55) 59(16.5,0) 60(16.75,-7.55) 61(17,0) 62(17.25,-7.55) 63(17.5,0) 64(17.75,-7.55) 65(18,0) 66(18.25,-7.55) 67(18.5,0)
  rect 1.194x2.743 smd: 68(-1.1,-0.775) 69(19.6,-0.775)
C_0201
  rect 0.381x0.356 smd: 1(0,0) 2(0.584,0)
C_0402
  rect 0.508x0.559 smd: 1(0,0) 2(0.914,0)
C_0603
  rect 0.635x0.889 smd: 1(0,0) 2(1.397,0)
C_0805
  rect 0.813x1.397 smd: 1(0,0) 2(1.702,0)
C_1206
  rect 1.016x1.651 smd: 1(0,0) 2(2.667,0)
C_1808
  rect 1.041x2.311 smd: 1(0,0) 2(4.35,0)
C_B2
  rect 1.346x2.692 smd: 1(0,0) 2(-2.75,0)
C_D
  rect 2.388x2.896 smd: 1(0,0) 2(6.1,0)
C_D2
  rect 2.388x2.794 smd: 1(0,0) 2(6.4,0)
C_D3
  rect 2.388x2.794 smd: 1(0,0) 2(6.4,0)
CSD97374CQ4M_SON8_3P5X4P5
  oval 0.203x0.889 smd: 1(0,0) 2(0.4,0) 3(0.8,0) 6(0.8,3.5) 7(0.4,3.5) 8(0,3.5)
  custom 0.225x0.225 smd: 4(2.2,0.262) 5(2.2,3.238)
  rect 4.039x2.21 smd: 9(1.6,1.75)
CVILU_CF4218FH0R0-05-NH_18P-T
  oval 0.305x0.787 smd: 1(0,0) 2(0.5,0) 3(1,0) 4(1.5,0) 5(2,0) 6(2.5,0) 7(3,0) 8(3.5,0) 9(4,0) 10(4.5,0) 11(5,0) 12(5.5,0) 13(6,0) 14(6.5,0) 15(7,0) 16(7.5,0) 17(8,0) 18(8.5,0)
  rect 0.406x0.787 smd: 19(-1,-2.5) 20(9.5,-2.5)
CVILU_CF5020FD0RK-05-NH_20P-T
  oval 0.305x0.94 smd: 1(0,0) 2(0.5,0) 3(1,0) 4(1.5,0) 5(2,0) 6(2.5,0) 7(3,0) 8(3.5,0) 9(4,0) 10(4.5,0) 11(5,0) 12(5.5,0) 13(6,0) 14(6.5,0) 15(7,0) 16(7.5,0) 17(8,0) 18(8.5,0) 19(9,0) 20(9.5,0)
  rect 1.651x1.397 smd: 21(-2.325,-3.375) 22(11.825,-3.375)
CVILU_CF5026FD0RK-05-NH_26P-T
  oval 0.305x0.94 smd: 1(0,0) 2(0.5,0) 3(1,0) 4(1.5,0) 5(2,0) 6(2.5,0) 7(3,0) 8(3.5,0) 9(4,0) 10(4.5,0) 11(5,0) 12(5.5,0) 13(6,0) 14(6.5,0) 15(7,0) 16(7.5,0) 17(8,0) 18(8.5,0) 19(9,0) 20(9.5,0) 21(10,0) 22(10.5,0) 23(11,0) 24(11.5,0) 25(12,0) 26(12.5,0)
  rect 1.651x1.397 smd: 27(14.825,-3.375) 28(-2.325,-3.375)
CVILU_CI0805M1HRC-NH_5P-T
  round 1.803 hole 1.803 unplated: (-0.2,5.2) (8.2,5.2)
  oval 0.889x2.388 smd: 1(0,0) 2(2,0) 3(4,0) 4(6,0) 5(8,0)
  rect 1.6x2.489 smd: 6(11.15,9.05) 7(-3.15,9.05)
CVILU_CI1804M1VRA-NH_4P
  oval 0.508x0.991 smd: 1(0,-0.05) 2(-0.8,-0.05) 3(-1.6,-0.05) 4(-2.4,-0.05)
  rect 1.194x1.702 smd: 5(-3.7,1.4) 6(1.3,1.4)
CYNTE_PCMB063T-1R0MS_2P
  rect 2.362x3.505 smd: 1(0,0) 2(6.05,0)
CYNTE_PCMB103T-2R2MS_2P
  rect 3.81x3.988 smd: 1(0,0) 2(9.2,0)
CYNTE_PCMC063T-1R5MN_2P
  rect 2.159x3.505 smd: 1(0,0) 2(5.85,0)
DB3J315E0L_SMINI3-F2-B3
  oval 0.889x0.787 smd: 1(0,0) 2(-0.65,-1.9) 3(0.65,-1.9)
DDTA114EUA-7-F_SOT323-3
  oval 0.813x0.914 smd: 1(0,0) 2(0.65,1.6) 3(-0.65,1.6)
DEREN_40-42251-01001RHF_10P-T
  oval 0.838x2.21 smd: 1(0,0.1) 2(1.5,0.1) 3(3,0.1) 4(4.5,0.1) 5(6,0.1) 6(7.5,0.1) 7(9,0.1) 8(10.5,0.1) 9(12,0.1) 10(13.5,0.1)
  custom 0.75x0.75 smd: 11(-3.4,-3.15) 12(16.9,-3.15)
DMN65D8LDW-7_SOT363-6
  oval 0.432x0.61 smd: 1(0,0) 2(0.65,0) 3(1.3,0) 4(1.3,1.9) 5(0.65,1.9) 6(0,1.9)
DMN65D8LW-7_SOT323-3
  oval 0.711x0.889 smd: 1(0,0) 2(-0.65,-1.9) 3(0.65,-1.9)
DMN66D0LDW-7_SOT363-6
  oval 0.432x0.61 smd: 1(0,0) 2(0.65,0) 3(1.3,0) 4(1.3,1.9) 5(0.65,1.9) 6(0,1.9)
E-T_4251K-F06N-40L_6P
  oval 0.406x0.991 smd: 1(0,0) 2(0.6,0) 3(1.2,0) 4(1.8,0) 5(2.4,0) 6(3,0)
  rect 0.711x1.041 smd: 7(3.95,-1.575) 8(-0.95,-1.575)
E-T_6601K-Y61N-04L_61P
  oval 0.305x1.245 smd: 1(0,0) 3(0.6,0) 5(1.2,0) 7(1.8,0) 9(2.4,0) 11(3,0) 13(3.6,0) 15(4.2,0) 17(4.8,0) 19(5.4,0) 21(6,0) 23(6.6,0) 25(7.2,0) 27(7.8,0) 29(8.4,0) 31(9,0) 33(9.6,0) 35(10.2,0) 37(10.8,0) 39(11.4,0) 41(12,0) 43(12.6,0) 45(13.2,0) 47(13.8,0) 49(14.4,0) 51(15,0) 53(15.6,0) 55(16.2,0) 57(16.8,0) 59(17.4,0) 61(18,0)
  oval 0.305x0.94 smd: 2(0.3,3.25) 4(0.9,3.25) 6(1.5,3.25) 8(2.1,3.25) 10(2.7,3.25) 12(3.3,3.25) 14(3.9,3.25) 16(4.5,3.25) 18(5.1,3.25) 20(5.7,3.25) 22(6.3,3.25) 24(6.9,3.25) 26(7.5,3.25) 28(8.1,3.25) 30(8.7,3.25) 32(9.3,3.25) 34(9.9,3.25) 36(10.5,3.25) 38(11.1,3.25) 40(11.7,3.25) 42(12.3,3.25) 44(12.9,3.25) 46(13.5,3.25) 48(14.1,3.25) 50(14.7,3.25) 52(15.3,3.25) 54(15.9,3.25) 56(16.5,3.25) 58(17.1,3.25) 60(17.7,3.25)
  rect 0.305x1.143 smd: 62(-0.65,0.6) 63(18.65,0.6)
E-T_6705K-Y20N-00L_20P
  oval 0.305x1.092 smd: 1(0,0) 2(-0.5,0) 3(-1,0) 4(-1.5,0) 5(-2,0) 6(-2.5,0) 7(-3,0) 8(-3.5,0) 9(-4,0) 10(-4.5,0) 11(-5,0) 12(-5.5,0) 13(-6,0) 14(-6.5,0) 15(-7,0) 16(-7.5,0) 17(-8,0) 18(-8.5,0) 19(-9,0) 20(-9.5,0)
  rect 0.991x2.007 smd: 21(2.1,-3.15) 22(-11.6,-3.15)
ESD8011MUT5G_X3DFN2-2-S
  rect 0.33x0.356 smd: 1(0,0) 2(0.43,0)
FDMC6679AZ_MLP8-5
  oval 0.432x0.711 smd: 1(0,0) 2(0.65,0) 3(1.3,0) 4(1.95,0)
  custom 0.537x0.537 smd: 5(0.975,2.075)
FDV301N-G_SOT23-3
  oval 1.016x1.524 smd: 1(0,0) 2(0.965,2.083) 3(-0.965,2.083)
FIDUCIAL_C40M80
  round 1.016 smd: 1(0,0)
G524B1T11U_SOT23-5
  oval 0.533x1.194 smd: 1(0,0) 2(0.95,0) 3(1.9,0) 4(1.9,3) 5(0,3)
H_1P0N
  round 0.991 hole 0.991 unplated: (0,0)
H_2P3N
  round 2.311 hole 2.311 unplated: (0,0)
H_2P3X2P7N
  oval 2.311x2.692 hole 2.311x2.692 unplated: (0,0)
H_2P6-G
  round 3.099 hole 2.591: 1(0,0)
H_3P1-G
  round 3.607 hole 3.099: 1(0,0)
H_3P2
  round 3.708 hole 3.2: 1(0,0)
H_3P4
  round 3.912 hole 3.404: 1(0,0)
H_3P5-G
  round 4.013 hole 3.505: 1(0,0)
H_3P8-G
  round 4.318 hole 3.81: 1(0,0)
HB_A531015-SCHR21_10P
  oval 0.305x0.889 smd: 1(0,0) 2(0.5,0) 3(1,0) 4(1.5,0) 5(2,0) 6(2.5,0) 7(3,0) 8(3.5,0) 9(4,0) 10(4.5,0)
  rect 0.991x2.007 smd: 11(6.6,-3.05) 12(-2.1,-3.05)
INPAQ_HCM2012GA900AE_4P
  rect 0.762x0.508 smd: 1(0,0) 2(1.85,0) 3(1.85,-0.9) 4(0,-0.9)
ISL62883CHRTZ-T_TQFN40_5X5-S
  oval 0.203x0.991 smd: 1(0,0) 2(0.4,0) 3(0.8,0) 4(1.2,0) 5(1.6,0) 6(2,0) 7(2.4,0) 8(2.8,0) 9(3.2,0) 10(3.6,0) 21(3.6,4.95) 22(3.2,4.95) 23(2.8,4.95) 24(2.4,4.95) 25(2,4.95) 26(1.6,4.95) 27(1.2,4.95) 28(0.8,4.95) 29(0.4,4.95) 30(0,4.95)
  oval 0.991x0.203 smd: 11(4.275,0.675) 12(4.275,1.075) 13(4.275,1.475) 14(4.275,1.875) 15(4.275,2.275) 16(4.275,2.675) 17(4.275,3.075) 18(4.275,3.475) 19(4.275,3.875) 20(4.275,4.275) 31(-0.675,4.275) 32(-0.675,3.875) 33(-0.675,3.475) 34(-0.675,3.075) 35(-0.675,2.675) 36(-0.675,2.275) 37(-0.675,1.875) 38(-0.675,1.475) 39(-0.675,1.075) 40(-0.675,0.675)
  rect 3.505x3.505 smd: 41(1.8,2.475)
ISL88738HRTZ-T_TQFN32_4X4
  oval 0.889x0.203 smd: 1(0,0) 2(0,-0.4) 3(0,-0.8) 4(0,-1.2) 5(0,-1.6) 6(0,-2) 7(0,-2.4) 8(0,-2.8) 17(4.1,-2.8) 18(4.1,-2.4) 19(4.1,-2) 20(4.1,-1.6) 21(4.1,-1.2) 22(4.1,-0.8) 23(4.1,-0.4) 24(4.1,0)
  oval 0.203x0.889 smd: 9(0.65,-3.45) 10(1.05,-3.45) 11(1.45,-3.45) 12(1.85,-3.45) 13(2.25,-3.45) 14(2.65,-3.45) 15(3.05,-3.45) 16(3.45,-3.45) 25(3.45,0.65) 26(3.05,0.65) 27(2.65,0.65) 28(2.25,0.65) 29(1.85,0.65) 30(1.45,0.65) 31(1.05,0.65) 32(0.65,0.65)
  rect 2.692x2.692 smd: 33(2.05,-1.4)
ISL95808HRZ-TS2378_DFN8_2X2-S
  oval 0.254x0.787 smd: 1(0,0) 2(0.5,0) 3(1,0) 4(1.5,0) 5(1.5,2.2) 6(1,2.2) 7(0.5,2.2) 8(0,2.2)
  rect 1.549x0.889 smd: 9(0.75,1.1)
IT8010FN-BX-R_QFN20_4X4
  oval 0.889x0.254 smd: 1(0,0) 2(0,-0.5) 3(0,-1) 4(0,-1.5) 5(0,-2) 11(4.1,-2) 12(4.1,-1.5) 13(4.1,-1) 14(4.1,-0.5) 15(4.1,0)
  oval 0.254x0.889 smd: 6(1.05,-3.05) 7(1.55,-3.05) 8(2.05,-3.05) 9(2.55,-3.05) 10(3.05,-3.05) 16(3.05,1.05) 17(2.55,1.05) 18(2.05,1.05) 19(1.55,1.05) 20(1.05,1.05)
  rect 2.565x2.565 smd: 21(2.05,-1)
JAE_DX07B024XJ1R1300_24P
  round 0.711 hole 0.711 unplated: (-0.85,-0.66)
  oval 0.94x0.711 hole 0.94x0.711 unplated: (6.35,-0.66)
  oval 1.092x1.956 hole 0.61x1.448: 1(-2.05,-1.535) 2(7.55,-1.535)
  oval 1.092x2.388 hole 0.61x1.6: 3(-3.05,-5.76) 4(8.55,-5.76)
  oval 0.305x1.092 smd: A1(0,0) A2(0.5,0) A3(1,0) A4(1.5,0) A5(2,0) A6(2.5,0) A7(3,0) A8(3.5,0) A9(4,0) A10(4.5,0) A11(5,0) A12(5.5,0)
  round 0.61 hole 0.406: B1(5.55,-1.21) B2(5.15,-2.01) B3(4.35,-2.01) B4(4.1,-1.21) B5(3.55,-2.01) B6(3.15,-1.21) B7(2.35,-1.21) B8(1.95,-2.01) B9(1.4,-1.21) B10(1.15,-2.01) B11(0.35,-2.01) B12(-0.05,-1.21)
JAE_SF51S006V4DR1000Q_8P
  round 0.762 hole 0.762 unplated: (-2.19,-10.215)
  round 0.889 hole 0.889 unplated: (7.01,2.835)
  rect 0.991x0.838 smd: 1(10.765,-9.44)
  rect 0.889x0.61 smd: 2(-2.94,3.715)
  rect 1.245x1.803 smd: 3(-3.39,-13.165)
  rect 1.245x1.397 smd: 4(-3.39,-5.165)
  rect 1.295x1.016 smd: 5(-0.715,3.725) 6(9.535,3.725)
  rect 1.041x1.397 smd: 7(12.1,1.025)
  rect 0.94x1.397 smd: 8(12.55,-6.465)
  rect 1.219x1.143 smd: 9(10.795,-13.49)
  rect 0.889x0.762 smd: C1(0,0) C2(2.54,0) C3(5.08,0) C4(7.62,0) C5(0,-13.15) C6(2.54,-13.15) C7(5.08,-13.15) C8(7.62,-13.15)
JUMP_43X39
  custom 0.191x0.191 smd: 1(0,0) 2(0.914,0)
JUMP_43X79
  custom 0.188x0.188 smd: 1(0,0) 2(1.1,0)
JUMP_43X118
  custom 0.187x0.187 smd: 1(0,0) 2(1.1,0)
JUMP_43X118-NPM
  custom 0.187x0.187 smd: 1(0,0) 2(1.1,0)
L2N7002WT1G_SC-70-3
  oval 0.711x0.889 smd: 1(0,0) 2(-0.65,-1.9) 3(0.65,-1.9)
L03ESDL5V0CC3-2_SOT23-3
  oval 1.016x1.524 smd: 1(0,0) 2(0.965,2.083) 3(-0.965,2.083)
L05ESDL5V0NA-4_SLP2510P8-10-9
  rect 0.203x0.686 smd: 1(0,0) 2(-0.5,0) 4(-1.5,0) 5(-2,0) 6(-2,-0.875) 7(-1.5,-0.875) 8(-0.5,-0.875) 9(0,-0.875)
  rect 0.406x1.549 smd: 3(-1,-0.437)
L30ESD24VC3-2_SOT23-3
  oval 1.016x1.524 smd: 1(0,0) 2(0.965,2.083) 3(-0.965,2.083)
LCN_DAN05-67306-0100_75P
  round 1.092 hole 1.092 unplated: (-0.75,-5.275)
  round 1.6 hole 1.6 unplated: (19.25,-5.275)
  oval 0.305x1.549 smd: 1(0,0) 2(0.25,-7.55) 3(0.5,0) 4(0.75,-7.55) 5(1,0) 6(1.25,-7.55) 7(1.5,0) 16(3.75,-7.55) 17(4,0) 18(4.25,-7.55) 19(4.5,0) 20(4.75,-7.55) 21(5,0) 22(5.25,-7.55) 23(5.5,0) 24(5.75,-7.55) 25(6,0) 26(6.25,-7.55) 27(6.5,0) 28(6.75,-7.55) 29(7,0) 30(7.25,-7.55) 31(7.5,0) 32(7.75,-7.55) 33(8,0) 34(8.25,-7.55) 35(8.5,0) 36(8.75,-7.55) 37(9,0) 38(9.25,-7.55) 39(9.5,0) 40(9.75,-7.55) 41(10,0) 42(10.25,-7.55) 43(10.5,0) 44(10.75,-7.55) 45(11,0) 46(11.25,-7.55) 47(11.5,0) 48(11.75,-7.55) 49(12,0) 50(12.25,-7.55) 51(12.5,0) 52(12.75,-7.55) 53(13,0) 54(13.25,-7.55) 55(13.5,0) 56(13.75,-7.55) 57(14,0) 58(14.25,-7.55) 59(14.5,0) 60(14.75,-7.55) 61(15,0) 62(15.25,-7.55) 63(15.5,0) 64(15.75,-7.55) 65(16,0) 66(16.25,-7.55) 67(16.5,0) 68(16.75,-7.55) 69(17,0) 70(17.25,-7.55) 71(17.5,0) 72(17.75,-7.55) 73(18,0) 74(18.25,-7.55) 75(18.5,0)
  rect 1.194x2.743 smd: 76(19.6,-0.775) 77(-1.1,-0.775)
LCN_DAN05-Q0406-0103_260P
  round 1.092 hole 1.092 unplated: (-67.775,-4.1)
  round 1.6 hole 1.6 unplated: (1.025,-4.1)
  oval 0.305x1.753 smd: 1(0,0) 2(-0.25,-8.2) 3(-0.5,0) 4(-0.75,-8.2) 5(-1,0) 6(-1.25,-8.2) 7(-1.5,0) 8(-1.75,-8.2) 9(-2,0) 10(-2.25,-8.2) 11(-2.5,0) 12(-2.75,-8.2) 13(-3,0) 14(-3.25,-8.2) 15(-3.5,0) 16(-3.75,-8.2) 17(-4,0) 18(-4.25,-8.2) 19(-4.5,0) 20(-4.75,-8.2) 21(-5,0) 22(-5.25,-8.2) 23(-5.5,0) 24(-5.75,-8.2) 25(-6,0) 26(-6.25,-8.2) 27(-6.5,0) 28(-6.75,-8.2) 29(-7,0) 30(-7.25,-8.2) 31(-7.5,0) 32(-7.75,-8.2) 33(-8,0) 34(-8.25,-8.2) 35(-8.5,0) 36(-8.75,-8.2) 37(-9,0) 38(-9.25,-8.2) 39(-9.5,0) 40(-9.75,-8.2) 41(-10,0) 42(-10.25,-8.2) 43(-10.5,0) 44(-10.75,-8.2) 45(-11,0) 46(-11.25,-8.2) 47(-11.5,0) 48(-11.75,-8.2) 49(-12,0) 50(-12.25,-8.2) 51(-12.5,0) 52(-12.75,-8.2) 53(-13,0) 54(-13.25,-8.2) 55(-13.5,0) 56(-13.75,-8.2) 57(-14,0) 58(-14.25,-8.2) 59(-14.5,0) 60(-14.75,-8.2) 61(-15,0) 62(-15.25,-8.2) 63(-15.5,0) 64(-15.75,-8.2) 65(-16,0) 66(-16.25,-8.2) 67(-16.5,0) 68(-16.75,-8.2) 69(-17,0) 70(-17.25,-8.2) 71(-17.5,0) 72(-17.75,-8.2) 73(-18,0) 74(-18.25,-8.2) 75(-18.5,0) 76(-18.75,-8.2) 77(-19,0) 78(-19.25,-8.2) 79(-19.5,0) 80(-19.75,-8.2) 81(-20,0) 82(-20.25,-8.2) 83(-20.5,0) 84(-20.75,-8.2) 85(-21,0) 86(-21.25,-8.2) 87(-21.5,0) 88(-21.75,-8.2) 89(-22,0) 90(-22.25,-8.2) 91(-22.5,0) 92(-22.75,-8.2) 93(-23,0) 94(-23.25,-8.2) 95(-23.5,0) 96(-23.75,-8.2) 97(-24,0) 98(-24.25,-8.2) 99(-24.5,0) 100(-24.75,-8.2) 101(-25,0) 102(-25.25,-8.2) 103(-25.5,0) 104(-25.75,-8.2) 105(-26,0) 106(-26.25,-8.2) 107(-26.5,0) 108(-26.75,-8.2) 109(-27,0) 110(-27.25,-8.2) 111(-27.5,0) 112(-27.75,-8.2) 113(-28,0) 114(-28.25,-8.2) 115(-28.5,0) 116(-28.75,-8.2) 117(-29,0) 118(-29.25,-8.2) 119(-29.5,0) 120(-29.75,-8.2) 121(-30,0) 122(-30.25,-8.2) 123(-30.5,0) 124(-30.75,-8.2) 125(-31,0) 126(-31.25,-8.2) 127(-31.5,0) 128(-31.75,-8.2) 129(-32,0) 130(-32.25,-8.2) 131(-32.5,0) 132(-32.75,-8.2) 133(-33,0) 134(-33.25,-8.2) 135(-33.5,0) 136(-33.75,-8.2) 137(-34,0) 138(-34.25,-8.2) 139(-34.5,0) 140(-34.75,-8.2) 141(-35,0) 142(-35.25,-8.2) 143(-35.5,0) 144(-35.75,-8.2) 145(-38,0) 146(-38.25,-8.2) 147(-38.5,0) 148(-38.75,-8.2) 149(-39,0) 150(-39.25,-8.2) 151(-39.5,0) 152(-39.75,-8.2) 153(-40,0) 154(-40.25,-8.2) 155(-40.5,0) 156(-40.75,-8.2) 157(-41,0) 158(-41.25,-8.2) 159(-41.5,0) 160(-41.75,-8.2) 161(-42,0) 162(-42.25,-8.2) 163(-42.5,0) 164(-42.75,-8.2) 165(-43,0) 166(-43.25,-8.2) 167(-43.5,0) 168(-43.75,-8.2) 169(-44,0) 170(-44.25,-8.2) 171(-44.5,0) 172(-44.75,-8.2) 173(-45,0) 174(-45.25,-8.2) 175(-45.5,0) 176(-45.75,-8.2) 177(-46,0) 178(-46.25,-8.2) 179(-46.5,0) 180(-46.75,-8.2) 181(-47,0) 182(-47.25,-8.2) 183(-47.5,0) 184(-47.75,-8.2) 185(-48,0) 186(-48.25,-8.2) 187(-48.5,0) 188(-48.75,-8.2) 189(-49,0) 190(-49.25,-8.2) 191(-49.5,0) 192(-49.75,-8.2) 193(-50,0) 194(-50.25,-8.2) 195(-50.5,0) 196(-50.75,-8.2) 197(-51,0) 198(-51.25,-8.2) 199(-51.5,0) 200(-51.75,-8.2) 201(-52,0) 202(-52.25,-8.2) 203(-52.5,0) 204(-52.75,-8.2) 205(-53,0) 206(-53.25,-8.2) 207(-53.5,0) 208(-53.75,-8.2) 209(-54,0) 210(-54.25,-8.2) 211(-54.5,0) 212(-54.75,-8.2) 213(-55,0) 214(-55.25,-8.2) 215(-55.5,0) 216(-55.75,-8.2) 217(-56,0) 218(-56.25,-8.2) 219(-56.5,0) 220(-56.75,-8.2) 221(-57,0) 222(-57.25,-8.2) 223(-57.5,0) 224(-57.75,-8.2) 225(-58,0) 226(-58.25,-8.2) 227(-58.5,0) 228(-58.75,-8.2) 229(-59,0) 230(-59.25,-8.2) 231(-59.5,0) 232(-59.75,-8.2) 233(-60,0) 234(-60.25,-8.2) 235(-60.5,0) 236(-60.75,-8.2) 237(-61,0) 238(-61.25,-8.2) 239(-61.5,0) 240(-61.75,-8.2) 241(-62,0) 242(-62.25,-8.2) 243(-62.5,0) 244(-62.75,-8.2) 245(-63,0) 246(-63.25,-8.2) 247(-63.5,0) 248(-63.75,-8.2) 249(-64,0) 250(-64.25,-8.2) 251(-64.5,0) 252(-64.75,-8.2) 253(-65,0) 254(-65.25,-8.2) 255(-65.5,0) 256(-65.75,-8.2) 257(-66,0) 258(-66.25,-8.2) 259(-66.5,0) 260(-66.75,-8.2)
  rect 3.505x4.597 smd: 261(0.425,7.9) 262(-67.175,7.9)
LED_LTW-C193DC-C_2P
  rect 0.787x0.787 smd: 1(0,0) 2(1.5,0)
LM393DGKR_VSSOP8
  oval 1.575x0.381 smd: 1(0,0) 2(0,-0.65) 3(0,-1.3) 4(0,-1.95) 5(4.35,-1.95) 6(4.35,-1.3) 7(4.35,-0.65) 8(4.35,0)
LOTES_APCI0170-P001A_75P
  round 1.143 hole 1.143 unplated: (-1.75,-1.55)
  round 1.651 hole 1.651 unplated: (20.25,-1.55)
  oval 0.305x1.499 smd: 1(0,0) 3(0.5,0) 5(1,0) 7(1.5,0) 9(2,0) 11(2.5,0) 13(3,0) 15(3.5,0) 17(4,0) 19(4.5,0) 21(5,0) 23(5.5,0) 25(6,0) 27(6.5,0) 29(7,0) 31(7.5,0) 33(8,0) 35(8.5,0) 37(9,0) 39(9.5,0) 41(10,0) 43(10.5,0) 45(11,0) 47(11.5,0) 49(12,0) 51(12.5,0) 53(13,0) 55(13.5,0) 57(14,0) 67(16.5,0) 69(17,0) 71(17.5,0) 73(18,0) 75(18.5,0)
  round 0.762 hole 0.508: 2(0.25,-2.85) 4(0.75,-2.05) 6(1.25,-2.85) 8(1.75,-2.05) 10(2.25,-2.85) 12(2.75,-2.05) 14(3.25,-2.85) 16(3.75,-2.05) 18(4.25,-2.85) 20(4.75,-2.05) 22(5.25,-2.85) 24(5.75,-2.05) 26(6.25,-2.85) 28(6.75,-2.05) 30(7.25,-2.85) 32(7.75,-2.05) 34(8.25,-2.85) 36(8.75,-2.05) 38(9.25,-2.85) 40(9.75,-2.05) 42(10.25,-2.85) 44(10.75,-2.05) 46(11.25,-2.85) 48(11.75,-2.05) 50(12.25,-2.85) 52(12.75,-2.05) 54(13.25,-2.85) 56(13.75,-2.05) 58(14.25,-2.85) 68(16.75,-2.05) 70(17.25,-2.85) 72(17.75,-2.05) 74(18.25,-2.85)
  rect 1.194x2.743 smd: 76(20.635,-6.52) 77(-2.135,-6.52)
LP2301ALT1G_SOT23-3
  oval 1.016x1.524 smd: 1(0,0) 2(0.965,2.083) 3(-0.965,2.083)
MAG_MLV-FY12N1R0M-O1L_2P
  rect 0.889x2.489 smd: 1(0,0) 2(2.6,0)
MAG_MMD05CZR47M_4P
  custom 0.54x0.54 smd: 1(0,0) 4(4.35,0)
  rect 0.762x0.508 smd: 2(0.699,0) 3(3.652,0)
MAG_MMD06CZER15MG_4P
  custom 0.686x0.686 smd: 1(0,0) 4(8.509,0)
  rect 2.362x0.508 smd: 2(1.448,0) 3(7.061,0)
MAG_MMD-05CZ-R68M-X2L_2P
  rect 1.905x2.794 smd: 1(0,0) 2(4.1,0)
MAGLA_MMD-05CZ-1R0M-M7L_2P
  rect 1.905x2.794 smd: 1(0,0) 2(4.1,0)
MEC5105_WFBGA_169P
  round 0.343 smd: A1(0,0) A2(0.8,0) A3(1.6,0) A4(2.4,0) A5(3.2,0) A6(4,0) A7(4.801,0) A8(5.601,0) A9(6.401,0) A10(7.201,0) A11(8.001,0) A12(8.801,0) A13(9.601,0) B1(0,-0.8) B2(0.8,-0.8) B3(1.6,-0.8) B4(2.4,-0.8) B5(3.2,-0.8) B6(4,-0.8) B7(4.801,-0.8) B8(5.601,-0.8) B9(6.401,-0.8) B10(7.201,-0.8) B11(8.001,-0.8) B12(8.801,-0.8) B13(9.601,-0.8) C1(0,-1.6) C2(0.8,-1.6) C3(1.6,-1.6) C4(2.4,-1.6) C5(3.2,-1.6) C6(4,-1.6) C7(4.801,-1.6) C8(5.601,-1.6) C9(6.401,-1.6) C10(7.201,-1.6) C11(8.001,-1.6) C12(8.801,-1.6) C13(9.601,-1.6) D1(0,-2.4) D2(0.8,-2.4) D3(1.6,-2.4) D4(2.4,-2.4) D5(3.2,-2.4) D6(4,-2.4) D7(4.801,-2.4) D8(5.601,-2.4) D9(6.401,-2.4) D10(7.201,-2.4) D11(8.001,-2.4) D12(8.801,-2.4) D13(9.601,-2.4) E1(0,-3.2) E2(0.8,-3.2) E3(1.6,-3.2) E4(2.4,-3.2) E5(3.2,-3.2) E6(4,-3.2) E7(4.801,-3.2) E8(5.601,-3.2) E9(6.401,-3.2) E10(7.201,-3.2) E11(8.001,-3.2) E12(8.801,-3.2) E13(9.601,-3.2) F1(0,-4) F2(0.8,-4) F3(1.6,-4) F4(2.4,-4) F5(3.2,-4) F6(4,-4) F7(4.801,-4) F8(5.601,-4) F9(6.401,-4) F10(7.201,-4) F11(8.001,-4) F12(8.801,-4) F13(9.601,-4) G1(0,-4.801) G2(0.8,-4.801) G3(1.6,-4.801) G4(2.4,-4.801) G5(3.2,-4.801) G6(4,-4.801) G7(4.801,-4.801) G8(5.601,-4.801) G9(6.401,-4.801) G10(7.201,-4.801) G11(8.001,-4.801) G12(8.801,-4.801) G13(9.601,-4.801) H1(0,-5.601) H2(0.8,-5.601) H3(1.6,-5.601) H4(2.4,-5.601) H5(3.2,-5.601) H6(4,-5.601) H7(4.801,-5.601) H8(5.601,-5.601) H9(6.401,-5.601) H10(7.201,-5.601) H11(8.001,-5.601) H12(8.801,-5.601) H13(9.601,-5.601) J1(0,-6.401) J2(0.8,-6.401) J3(1.6,-6.401) J4(2.4,-6.401) J5(3.2,-6.401) J6(4,-6.401) J7(4.801,-6.401) J8(5.601,-6.401) J9(6.401,-6.401) J10(7.201,-6.401) J11(8.001,-6.401) J12(8.801,-6.401) J13(9.601,-6.401) K1(0,-7.201) K2(0.8,-7.201) K3(1.6,-7.201) K4(2.4,-7.201) K5(3.2,-7.201) K6(4,-7.201) K7(4.801,-7.201) K8(5.601,-7.201) K9(6.401,-7.201) K10(7.201,-7.201) K11(8.001,-7.201) K12(8.801,-7.201) K13(9.601,-7.201) L1(0,-8.001) L2(0.8,-8.001) L3(1.6,-8.001) L4(2.4,-8.001) L5(3.2,-8.001) L6(4,-8.001) L7(4.801,-8.001) L8(5.601,-8.001) L9(6.401,-8.001) L10(7.201,-8.001) L11(8.001,-8.001) L12(8.801,-8.001) L13(9.601,-8.001) M1(0,-8.801) M2(0.8,-8.801) M3(1.6,-8.801) M4(2.4,-8.801) M5(3.2,-8.801) M6(4,-8.801) M7(4.801,-8.801) M8(5.601,-8.801) M9(6.401,-8.801) M10(7.201,-8.801) M11(8.001,-8.801) M12(8.801,-8.801) M13(9.601,-8.801) N1(0,-9.601) N2(0.8,-9.601) N3(1.6,-9.601) N4(2.4,-9.601) N5(3.2,-9.601) N6(4,-9.601) N7(4.801,-9.601) N8(5.601,-9.601) N9(6.401,-9.601) N10(7.201,-9.601) N11(8.001,-9.601) N12(8.801,-9.601) N13(9.601,-9.601)
MHPC_NS692417_24P
  oval 0.762x2.057 smd: 1(0,0) 2(1.27,0) 3(2.54,0) 4(3.81,0) 5(5.08,0) 6(6.35,0) 7(7.62,0) 8(8.89,0) 9(10.16,0) 10(11.43,0) 11(12.7,0) 12(13.97,0) 13(13.97,9.365) 14(12.7,9.365) 15(11.43,9.365) 16(10.16,9.365) 17(8.89,9.365) 18(7.62,9.365) 19(6.35,9.365) 20(5.08,9.365) 21(3.81,9.365) 22(2.54,9.365) 23(1.27,9.365) 24(0,9.365)
MMBT3904WT1G_SC70-3
  oval 0.711x0.889 smd: 1(0,0) 2(0.65,1.9) 3(-0.65,1.9)
MMST3904-7-F_SOT323-3
  oval 0.711x0.889 smd: 1(0,0) 2(0.65,1.9) 3(-0.65,1.9)
MURAT_BLM15AG102SN1D_2P
  rect 0.457x0.508 smd: 1(0,0) 2(0.85,0)
MURAT_BLM15GA750SN1D_2P
  rect 0.508x0.762 smd: 1(0,0) 2(0.75,0)
MURAT_BLM15PX221SN1D_2P
  rect 0.457x0.508 smd: 1(0,0) 2(0.85,0)
MURAT_BLM15PX330SN1D_2P
  rect 0.457x0.508 smd: 1(0,0) 2(0.85,0)
MURAT_BLM15PX600SN1D_2P
  rect 0.457x0.508 smd: 1(0,0) 2(0.85,0)
MURAT_LQG15HN12NJ02D_2P
  rect 0.533x0.559 smd: 1(0,0) 2(0.925,0)
NPCT650JB2YX_QFN32_5X5
  oval 0.889x0.254 smd: 1(0,0) 2(0,-0.5) 3(0,-1) 4(0,-1.5) 5(0,-2) 6(0,-2.5) 7(0,-3) 8(0,-3.5) 17(5.1,-3.5) 18(5.1,-3) 19(5.1,-2.5) 20(5.1,-2) 21(5.1,-1.5) 22(5.1,-1) 23(5.1,-0.5) 24(5.1,0)
  oval 0.254x0.889 smd: 9(0.8,-4.3) 10(1.3,-4.3) 11(1.8,-4.3) 12(2.3,-4.3) 13(2.8,-4.3) 14(3.3,-4.3) 15(3.8,-4.3) 16(4.3,-4.3) 25(4.3,0.8) 26(3.8,0.8) 27(3.3,0.8) 28(2.8,0.8) 29(2.3,0.8) 30(1.8,0.8) 31(1.3,0.8) 32(0.8,0.8)
  rect 3.505x3.505 smd: 33(2.55,-1.75)
NTR4502PT1G_SOT23-3
  oval 1.016x1.524 smd: 1(0,0) 2(0.965,2.083) 3(-0.965,2.083)
PANAS_EXC24CQ900U_4P
  rect 0.356x0.559 smd: 1(0,0) 2(0,-1.25) 3(-0.6,-1.25) 4(-0.6,0)
PDS5100H-13_POWERDI5-3
  rect 4.851x3.353 smd: 1(0,0)
  rect 1.397x1.397 smd: 2(3.982,-0.92) 3(3.982,0.92)
PESD5V0U2BT_SOT23-3
  oval 1.016x1.524 smd: 1(0,0) 2(0.965,2.083) 3(-0.965,2.083)
PS8338BQFN60GTR-A0_QFN60_5X9-S
  oval 0.203x1.016 smd: 1(0,0) 2(0.4,0) 3(0.8,0) 4(1.2,0) 5(1.6,0) 6(2,0) 7(2.4,0) 8(2.8,0) 9(3.2,0) 10(3.6,0) 11(4,0) 12(4.4,0) 13(4.8,0) 14(5.2,0) 15(5.6,0) 16(6,0) 17(6.4,0) 18(6.8,0) 19(7.2,0) 20(7.6,0) 31(7.6,4.975) 32(7.2,4.975) 33(6.8,4.975) 34(6.4,4.975) 35(6,4.975) 36(5.6,4.975) 37(5.2,4.975) 38(4.8,4.975) 39(4.4,4.975) 40(4,4.975) 41(3.6,4.975) 42(3.2,4.975) 43(2.8,4.975) 44(2.4,4.975) 45(2,4.975) 46(1.6,4.975) 47(1.2,4.975) 48(0.8,4.975) 49(0.4,4.975) 50(0,4.975)
  oval 1.016x0.203 smd: 21(8.288,0.688) 22(8.288,1.088) 23(8.288,1.488) 24(8.288,1.888) 25(8.288,2.288) 26(8.288,2.688) 27(8.288,3.088) 28(8.288,3.488) 29(8.288,3.888) 30(8.288,4.288) 51(-0.688,4.288) 52(-0.688,3.888) 53(-0.688,3.488) 54(-0.688,3.088) 55(-0.688,2.688) 56(-0.688,2.288) 57(-0.688,1.888) 58(-0.688,1.488) 59(-0.688,1.088) 60(-0.688,0.688)
  rect 7.01x2.997 smd: 61(3.8,2.488)
R0402_0OHM
  rect 0.508x0.559 smd: 1(0,0) 2(0.914,0)
R0603_0OHM
  rect 0.635x0.889 smd: 1(0,0) 2(1.397,0)
R_0201
  rect 0.381x0.356 smd: 1(0,0) 2(0.584,0)
R_0402
  rect 0.508x0.559 smd: 1(0,0) 2(0.914,0)
R_0603
  rect 0.635x0.889 smd: 1(0,0) 2(1.397,0)
R_0805
  rect 0.813x1.397 smd: 1(0,0) 2(1.702,0)
R_1206
  rect 1.016x1.651 smd: 1(0,0) 2(2.667,0)
R_1206_4P-D
  custom 0.371x0.371 smd: 1(0,0) 4(3.327,0)
  custom 0.114x0.114 smd: 2(0.775,0) 3(2.553,0)
RB520SM-30T2R_EMD2-2
  rect 0.61x0.787 smd: 1(0,0) 2(1.7,0)
RB751S40T1G_SOD523-2
  rect 0.406x0.406 smd: 1(0,0) 2(1.4,0)
RP_0804_8P4R
  oval 0.66x0.254 smd: 1(0,0) 2(0,-0.5) 3(0,-1) 4(0,-1.5) 5(1.15,-1.5) 6(1.15,-1) 7(1.15,-0.5) 8(1.15,0)
RT8097ALGE_SOT23-6
  oval 0.711x0.991 smd: 1(0,0) 2(0.95,0) 3(1.9,0) 4(1.9,2.6) 5(0.95,2.6) 6(0,2.6)
RTS5242-GR_QFN32_4X4-S
  oval 0.889x0.203 smd: 1(0,0) 2(0,-0.4) 3(0,-0.8) 4(0,-1.2) 5(0,-1.6) 6(0,-2) 7(0,-2.4) 8(0,-2.8) 17(4.1,-2.8) 18(4.1,-2.4) 19(4.1,-2) 20(4.1,-1.6) 21(4.1,-1.2) 22(4.1,-0.8) 23(4.1,-0.4) 24(4.1,0)
  oval 0.203x0.889 smd: 9(0.65,-3.45) 10(1.05,-3.45) 11(1.45,-3.45) 12(1.85,-3.45) 13(2.25,-3.45) 14(2.65,-3.45) 15(3.05,-3.45) 16(3.45,-3.45) 25(3.45,0.65) 26(3.05,0.65) 27(2.65,0.65) 28(2.25,0.65) 29(1.85,0.65) 30(1.45,0.65) 31(1.05,0.65) 32(0.65,0.65)
  rect 2.692x2.692 smd: 33(2.05,-1.4)
SANTA_130470-19_13P-T
  round 1.295 hole 0.889: 1(0,0) 2(-1.02,1.1) 3(-2.04,0) 4(-3.06,1.1) 5(-4.08,0) 6(-5.1,1.1) 7(-6.12,0) 8(-7.14,1.1)
  round 1.397 hole 0.991: 9(4.93,0) 10(7.22,0) 11(-14.36,0) 12(-13.215,-1.5) 13(-12.07,0)
  custom 0.425x0.425 hole 0.711x2.388: 14(9.63,-7.275) 15(9.63,-13.125) 16(-16.77,-7.275) 17(-16.77,-13.125)
SDMK0340L-7-F_SOD323-2
  rect 1.346x0.66 smd: 1(0,0) 2(2.4,0)
SHORTPADS
  custom 0.19x0.19 smd: 1(-0.483,0) 2(0.483,0)
SHORTPADS-NPM
  custom 0.19x0.19 smd: 1(-0.483,0) 2(0.483,0)
SINGA_2SJ3095-085111F_6P
  oval 0.991x1.803 hole 0.61x1.397: 1(0,0) 2(-9.5,5.5) 3(0,5.2) 4(0,7.8) 5(-9.5,0) 6(-9.5,2.75) 7(0,2.65)
SKL-U_BGA_1356P-T
  round 0.356 smd: A3(-0.965,0) A70(-40.166,0) B2(-0.483,0.483) B71(-40.629,0.462) BA1(0,22.166) BA71(-40.629,22.166) BB2(-0.462,22.628) BB70(-40.166,22.628) C1(0,0.965)
  round 0.33 smd: A4(-1.615,0) A69(-39.516,0) AY1(0,21.516) AY71(-40.629,21.516) B3(-1.118,0.635) B70(-39.999,0.63) BA2(-0.629,21.999) BA70(-39.999,21.999) BB3(-1.113,22.628) BB69(-39.516,22.628) C2(-0.635,1.118) C71(-40.629,1.113) D1(0,1.615)
  round 0.305 smd: A5(-2.266,0) A68(-38.866,0) AA2(-0.975,10.804) AA4(-1.951,10.804) AA63(-35.427,10.719) AA64(-36.077,10.719) AA65(-36.727,10.719) AA66(-37.377,10.719) AA67(-38.028,10.719) AA68(-38.678,10.719) AA69(-39.328,10.719) AA70(-39.978,10.719) AA71(-40.629,10.719) AB4(-1.951,11.467) AB6(-2.729,11.181) AB7(-3.379,11.181) AB8(-4.029,11.181) AB9(-4.679,11.181) AB10(-5.33,11.181) AB11(-5.98,11.181) AB12(-6.63,11.181) AB13(-7.28,11.181) AB15(-8.126,11.305) AB16(-8.776,11.305) AB17(-9.426,11.305) AB18(-10.077,11.305) AB19(-10.727,11.305) AB20(-11.377,11.305) AB21(-12.027,11.305) AB62(-34.958,11.176) AC3(-1.626,12.13) AC63(-35.427,11.633) AC64(-36.077,11.633) AC65(-36.727,11.633) AC66(-37.377,11.633) AC67(-38.028,11.633) AC68(-38.678,11.633) AC69(-39.328,11.633) AC70(-39.978,11.633) AC71(-40.629,11.633) AD4(-1.951,12.792) AD6(-2.729,12.248) AD7(-3.379,12.248) AD8(-4.029,12.248) AD9(-4.679,12.248) AD10(-5.33,12.248) AD11(-5.98,12.248) AD12(-6.63,12.248) AD13(-7.28,12.248) AD15(-8.126,12.143) AD16(-8.776,12.143) AD17(-9.426,12.143) AD18(-10.077,12.143) AD19(-10.727,12.143) AD20(-11.377,12.143) AD21(-12.027,12.143) AD62(-34.958,12.09) AE62(-34.958,13.005) AE63(-35.427,12.547) AE64(-36.077,12.547) AE65(-36.727,12.547) AE66(-37.377,12.547) AE67(-38.028,12.547) AE68(-38.678,12.547) AE69(-39.328,12.547) AF2(-0.975,13.455) AF4(-1.951,13.455) AF6(-2.729,13.315) AF7(-3.379,13.315) AF8(-4.029,13.315) AF9(-4.679,13.315) AF10(-5.33,13.315) AF11(-5.98,13.315) AF12(-6.63,13.315) AF13(-7.28,13.315) AF15(-8.126,12.982) AF16(-8.776,12.982) AF17(-9.426,12.982) AF18(-10.077,12.982) AF19(-10.727,12.982) AF20(-11.377,12.982) AF21(-12.027,12.982) AF63(-35.427,13.462) AF64(-36.077,13.462) AF65(-36.727,13.462) AF66(-37.377,13.462) AF67(-38.028,13.462) AF68(-38.678,13.253) AF69(-39.328,13.253) AG4(-1.951,14.118) AG15(-8.126,13.82) AG16(-8.776,13.82) AG17(-9.426,13.82) AG18(-10.077,13.82) AG19(-10.727,13.82) AG20(-11.377,13.82) AG21(-12.027,13.82) AG62(-34.958,13.919) AG69(-39.003,13.916) AH3(-1.626,14.781) AH6(-2.729,14.381) AH7(-3.379,14.381) AH8(-4.029,14.381) AH9(-4.679,14.381) AH10(-5.33,14.381) AH11(-5.98,14.381) AH12(-6.63,14.381) AH13(-7.28,14.381) AH63(-35.427,14.376) AH64(-36.077,14.376) AH65(-36.727,14.376) AH66(-37.377,14.376) AH67(-38.028,14.376) AJ4(-1.951,15.444) AJ15(-8.126,14.658) AJ16(-8.776,14.658) AJ17(-9.426,14.658) AJ18(-10.077,14.658) AJ19(-10.727,14.658) AJ20(-11.377,14.658) AJ21(-12.027,14.658) AJ62(-34.958,14.833) AK6(-2.729,15.321) AK7(-3.379,15.321) AK8(-4.029,15.321) AK9(-4.679,15.321) AK10(-5.33,15.321) AK11(-5.98,15.321) AK12(-6.63,15.321) AK13(-7.28,15.321) AK15(-8.126,15.496) AK16(-8.776,15.496) AK17(-9.426,15.496) AK18(-10.077,15.496) AK19(-10.727,15.496) AK20(-11.377,15.496) AK21(-12.027,15.496) AK22(-12.719,15.323) AK23(-13.633,15.323) AK25(-14.547,15.323) AK27(-15.462,15.323) AK28(-16.376,15.323) AK30(-17.291,15.323) AK32(-18.205,15.323) AK33(-19.119,15.323) AK35(-20.034,15.323) AK37(-20.948,15.323) AK38(-21.863,15.323) AK40(-22.777,15.323) AK42(-23.691,15.323) AK43(-24.606,15.323) AK45(-25.52,15.323) AK46(-26.435,15.323) AK48(-27.349,15.323) AK50(-28.263,15.323) AK52(-29.178,15.323) AK53(-30.092,15.323) AK55(-31.007,15.323) AK56(-31.921,15.323) AK58(-32.835,15.323) AK60(-33.75,15.323) AK62(-34.774,15.458) AK63(-35.427,15.291) AK64(-36.077,15.291) AK65(-36.727,15.291) AK66(-37.377,15.291) AK67(-38.028,15.291) AK68(-38.678,15.143) AK69(-39.653,15.143) AL2(-0.975,16.107) AL4(-1.951,16.107) AL23(-13.176,15.788) AL25(-14.09,15.788) AL27(-15.005,15.788) AL28(-15.919,15.788) AL30(-16.833,15.788) AL32(-17.748,15.788) AL33(-18.662,15.788) AL35(-19.577,15.788) AL37(-20.491,15.788) AL38(-21.405,15.788) AL40(-22.32,15.788) AL42(-23.234,15.788) AL43(-24.149,15.788) AL45(-25.063,15.788) AL46(-25.977,15.788) AL48(-26.892,15.788) AL50(-27.806,15.788) AL52(-28.721,15.788) AL53(-29.635,15.788) AL55(-30.549,15.788) AL56(-31.464,15.788) AL58(-32.378,15.788) AL60(-33.293,15.788) AL61(-34.207,15.788) AL63(-35.427,16.159) AL64(-36.077,16.159) AL65(-36.727,16.159) AL66(-37.377,16.159) AM4(-1.951,16.77) AM5(-2.66,16.261) AM7(-3.575,16.261) AM8(-4.489,16.261) AM10(-5.403,16.261) AM11(-6.318,16.261) AM13(-7.232,16.261) AM15(-8.147,16.261) AM16(-9.061,16.261) AM18(-9.975,16.261) AM20(-10.89,16.261) AM21(-11.804,16.261) AM22(-12.719,16.261) AM23(-13.633,16.261) AM25(-14.547,16.261) AM27(-15.462,16.261) AM28(-16.376,16.261) AM30(-17.291,16.261) AM32(-18.205,16.261) AM33(-19.119,16.261) AM35(-20.034,16.261) AM37(-20.948,16.261) AM38(-21.863,16.261) AM40(-22.777,16.261) AM42(-23.691,16.261) AM43(-24.606,16.261) AM45(-25.52,16.261) AM46(-26.435,16.261) AM48(-27.349,16.261) AM50(-28.263,16.261) AM52(-29.178,16.261) AM53(-30.092,16.261) AM55(-31.007,16.261) AM56(-31.921,16.261) AM58(-32.835,16.261) AM60(-33.75,16.261) AM61(-34.664,16.261) AM68(-38.353,16.37) AM69(-39.003,16.37) AN3(-1.626,17.433) AN5(-2.66,16.911) AN7(-3.575,16.911) AN8(-4.489,16.911) AN10(-5.403,16.911) AN11(-6.318,16.911) AN13(-7.232,16.911) AN15(-8.147,16.911) AN16(-9.061,16.911) AN18(-9.975,16.911) AN20(-10.89,16.911) AN21(-11.804,16.911) AN22(-12.719,16.911) AN23(-13.633,16.911) AN25(-14.547,16.911) AN27(-15.462,16.911) AN28(-16.376,16.911) AN30(-17.291,16.911) AN32(-18.205,16.911) AN33(-19.119,16.911) AN35(-20.034,16.911) AN37(-20.948,16.911) AN38(-21.863,16.911) AN40(-22.777,16.911) AN42(-23.691,16.911) AN43(-24.606,16.911) AN45(-25.52,16.911) AN46(-26.435,16.911) AN48(-27.349,16.911) AN50(-28.263,16.911) AN52(-29.178,16.911) AN53(-30.092,16.911) AN55(-31.007,16.911) AN56(-31.921,16.911) AN58(-32.835,16.911) AN60(-33.75,16.911) AN61(-34.664,16.911) AN63(-35.579,16.911) AN65(-36.493,16.911) AN66(-37.407,16.911) AN68(-38.678,17.033) AN69(-39.328,17.033) AP4(-1.951,18.096) AP5(-2.66,17.561) AP7(-3.575,17.561) AP8(-4.489,17.561) AP10(-5.403,17.561) AP11(-6.318,17.561) AP13(-7.232,17.561) AP15(-8.147,17.561) AP16(-9.061,17.561) AP18(-9.975,17.561) AP20(-10.89,17.561) AP21(-11.804,17.561) AP22(-12.719,17.561) AP23(-13.633,17.561) AP25(-14.547,17.561) AP27(-15.462,17.561) AP28(-16.376,17.561) AP30(-17.291,17.561) AP32(-18.205,17.561) AP33(-19.119,17.561) AP35(-20.034,17.561) AP37(-20.948,17.561) AP38(-21.863,17.561) AP40(-22.777,17.561) AP42(-23.691,17.561) AP43(-24.606,17.561) AP45(-25.52,17.561) AP46(-26.435,17.561) AP48(-27.349,17.561) AP50(-28.263,17.561) AP52(-29.178,17.561) AP53(-30.092,17.561) AP55(-31.007,17.561) AP56(-31.921,17.561) AP58(-32.835,17.561) AP60(-33.75,17.561) AP61(-34.664,17.561) AP63(-35.579,17.561) AP65(-36.493,17.561) AP66(-37.407,17.561) AP68(-38.353,17.646) AP70(-39.572,17.646) AR5(-2.66,18.211) AR7(-3.575,18.211) AR8(-4.489,18.211) AR10(-5.403,18.211) AR11(-6.318,18.211) AR13(-7.232,18.211) AR15(-8.147,18.211) AR16(-9.061,18.211) AR18(-9.975,18.211) AR20(-10.89,18.211) AR21(-11.804,18.211) AR22(-12.719,18.211) AR23(-13.633,18.211) AR25(-14.547,18.211) AR27(-15.462,18.211) AR28(-16.376,18.211) AR30(-17.291,18.211) AR32(-18.205,18.211) AR33(-19.119,18.211) AR35(-20.034,18.211) AR37(-20.948,18.211) AR38(-21.863,18.211) AR40(-22.777,18.211) AR42(-23.691,18.211) AR43(-24.606,18.211) AR45(-25.52,18.211) AR46(-26.435,18.211) AR48(-27.349,18.211) AR50(-28.263,18.211) AR52(-29.178,18.211) AR53(-30.092,18.211) AR55(-31.007,18.211) AR56(-31.921,18.211) AR58(-32.835,18.211) AR60(-33.75,18.211) AR61(-34.664,18.211) AR63(-35.579,18.211) AR65(-36.493,18.211) AR66(-37.407,18.211) AR68(-38.678,18.26) AR69(-39.328,18.26) AT2(-0.975,18.759) AT4(-1.951,18.759) AT5(-2.66,18.862) AT7(-3.575,18.862) AT8(-4.489,18.862) AT10(-5.403,18.862) AT11(-6.318,18.862) AT13(-7.232,18.862) AT15(-8.147,18.862) AT16(-9.061,18.862) AT18(-9.975,18.862) AT20(-10.89,18.862) AT21(-11.804,18.862) AT22(-12.719,18.862) AT23(-13.633,18.862) AT25(-14.547,18.862) AT27(-15.462,18.862) AT28(-16.376,18.862) AT30(-17.291,18.862) AT32(-18.205,18.862) AT33(-19.119,18.862) AT35(-20.034,18.862) AT37(-20.948,18.862) AT38(-21.863,18.862) AT40(-22.777,18.862) AT42(-23.691,18.862) AT43(-24.606,18.862) AT45(-25.52,18.862) AT46(-26.435,18.862) AT48(-27.349,18.862) AT50(-28.263,18.862) AT52(-29.178,18.862) AT53(-30.092,18.862) AT55(-31.007,18.862) AT56(-31.921,18.862) AT58(-32.835,18.862) AT60(-33.75,18.862) AT61(-34.664,18.862) AT63(-35.579,18.862) AT65(-36.493,18.862) AT66(-37.407,18.862) AT68(-38.353,18.823) AT69(-39.003,18.823) AU4(-1.951,19.422) AU5(-2.66,19.512) AU7(-3.575,19.512) AU8(-4.489,19.512) AU10(-5.403,19.512) AU11(-6.318,19.512) AU13(-7.232,19.512) AU15(-8.147,19.512) AU16(-9.061,19.512) AU18(-9.975,19.512) AU20(-10.89,19.512) AU21(-11.804,19.512) AU22(-12.719,19.512) AU23(-13.633,19.512) AU25(-14.547,19.512) AU27(-15.462,19.512) AU28(-16.376,19.512) AU30(-17.291,19.512) AU32(-18.205,19.512) AU33(-19.119,19.512) AU35(-20.034,19.512) AU37(-20.948,19.512) AU38(-21.863,19.512) AU40(-22.777,19.512) AU42(-23.691,19.512) AU43(-24.606,19.512) AU45(-25.52,19.512) AU46(-26.435,19.512) AU48(-27.349,19.512) AU50(-28.263,19.512) AU52(-29.178,19.512) AU53(-30.092,19.512) AU55(-31.007,19.512) AU56(-31.921,19.512) AU58(-32.835,19.512) AU60(-33.75,19.512) AU61(-34.664,19.512) AU63(-35.579,19.512) AU65(-36.493,19.512) AU66(-37.407,19.512) AV3(-1.626,20.113) AV68(-38.343,20.026) AV69(-39.328,20.215) AV70(-39.978,20.215) AW1(0,20.866) AW5(-2.534,20.226) AW6(-3.184,20.353) AW7(-3.75,20.678) AW8(-4.328,20.353) AW9(-4.898,20.678) AW10(-5.561,20.353) AW11(-6.171,20.678) AW12(-6.749,20.353) AW13(-7.319,20.678) AW14(-7.982,20.353) AW15(-8.592,20.678) AW16(-9.17,20.353) AW17(-9.74,20.678) AW18(-10.403,20.353) AW20(-11.012,20.678) AW21(-11.59,20.353) AW22(-12.16,20.678) AW23(-12.849,20.353) AW25(-13.486,20.678) AW26(-14.05,20.353) AW27(-14.713,20.678) AW28(-15.326,20.353) AW29(-15.94,20.678) AW30(-16.603,20.353) AW31(-17.167,20.678) AW32(-17.83,20.353) AW33(-18.467,20.678) AW34(-19.031,20.353) AW35(-19.694,20.678) AW36(-20.307,20.353) AW37(-20.921,20.678) AW38(-21.584,20.353) AW39(-22.148,20.678) AW41(-22.785,20.353) AW42(-23.423,20.678) AW43(-23.986,20.353) AW44(-24.649,20.678) AW45(-25.263,20.353) AW46(-25.876,20.678) AW47(-26.477,20.353) AW48(-27.041,20.678) AW49(-27.669,20.353) AW50(-28.298,20.678) AW51(-28.862,20.353) AW52(-29.463,20.678) AW53(-30.076,20.353) AW54(-30.69,20.678) AW55(-31.352,20.353) AW56(-31.916,20.678) AW57(-32.554,20.353) AW59(-33.191,20.678) AW60(-33.755,20.353) AW61(-34.418,20.678) AW62(-35.032,20.353) AW63(-35.645,20.678) AW64(-36.308,20.353) AW65(-36.872,20.678) AW66(-37.407,20.215) AW67(-38.332,20.685) AW68(-38.936,20.936) AW69(-39.581,20.85) AW70(-39.999,21.349) AW71(-40.629,20.866) AY2(-0.629,21.348) AY3(-1.286,21.342) AY4(-2.04,21.357) AY5(-2.649,21.003) AY8(-4.328,21.003) AY12(-6.749,21.003) AY16(-9.17,21.003) AY21(-11.59,21.003) AY26(-14.05,21.003) AY27(-14.713,21.328) AY29(-15.94,21.328) AY30(-16.603,21.003) AY34(-19.031,21.003) AY35(-19.694,21.328) AY37(-20.921,21.328) AY38(-21.584,21.003) AY43(-23.986,21.003) AY44(-24.649,21.328) AY46(-25.876,21.328) AY47(-26.477,21.003) AY51(-28.862,21.003) AY52(-29.463,21.328) AY54(-30.69,21.328) AY55(-31.352,21.003) AY60(-33.755,21.003) AY61(-34.418,21.328) AY63(-35.645,21.328) AY64(-36.308,21.003) AY66(-37.535,21.003) AY68(-38.85,21.581) B5(-2.266,0.65) B6(-2.847,0.975) B10(-5.325,0.975) B14(-7.803,0.975) B18(-10.281,0.975) B22(-12.759,0.975) B26(-15.237,0.975) B30(-17.715,0.975) B34(-20.194,0.975) B39(-22.672,0.975) B44(-25.15,0.975) B48(-27.628,0.975) B53(-30.106,0.975) B58(-32.584,0.975) B62(-35.062,0.975) B66(-37.54,0.975) B69(-39.349,0.63) BA3(-1.279,21.999) BA5(-2.599,21.94) BA8(-4.328,21.653) BA12(-6.749,21.653) BA16(-9.17,21.653) BA21(-11.59,21.653) BA23(-12.849,21.572) BA28(-15.326,21.572) BA32(-17.83,21.572) BA36(-20.307,21.572) BA41(-22.785,21.572) BA45(-25.263,21.572) BA49(-27.669,21.653) BA53(-30.076,21.572) BA57(-32.554,21.572) BA62(-35.032,21.572) BA68(-39.349,21.999) BB4(-1.763,22.628) BB68(-38.866,22.628) C4(-1.699,0.978) C5(-2.266,1.3) C7(-3.523,1.3) C8(-4.086,0.975) C9(-4.65,1.3) C11(-6.001,1.3) C12(-6.564,0.975) C13(-7.128,1.3) C15(-8.479,1.3) C16(-9.042,0.975) C17(-9.606,1.3) C19(-10.957,1.3) C20(-11.52,0.975) C21(-12.084,1.3) C23(-13.435,1.3) C24(-13.998,0.975) C25(-14.562,1.3) C27(-15.913,1.3) C28(-16.476,0.975) C29(-17.04,1.3) C31(-18.391,1.3) C32(-18.954,0.975) C33(-19.518,1.3) C36(-20.869,1.3) C37(-21.433,0.975) C38(-21.996,1.3) C40(-23.347,1.3) C41(-23.911,0.975) C42(-24.474,1.3) C45(-25.825,1.3) C46(-26.389,0.975) C47(-26.952,1.3) C50(-28.303,1.3) C51(-28.867,0.975) C52(-29.43,1.3) C54(-30.781,1.3) C55(-31.345,0.975) C56(-31.908,1.3) C59(-33.259,1.3) C60(-33.823,0.975) C61(-34.386,1.3) C63(-35.737,1.3) C64(-36.301,0.975) C65(-36.864,1.3) C67(-38.799,1.015) C68(-38.936,1.693) C70(-39.999,1.28) D3(-0.975,1.706) D4(-1.624,1.646) D5(-2.224,1.951) D6(-2.873,1.991) D7(-3.523,1.951) D8(-4.086,1.626) D9(-4.65,1.951) D10(-5.325,1.991) D11(-6.001,1.951) D12(-6.564,1.626) D13(-7.128,1.951) D14(-7.803,1.991) D15(-8.479,1.951) D16(-9.042,1.626) D17(-9.606,1.951) D18(-10.281,1.991) D19(-10.957,1.951) D20(-11.52,1.626) D21(-12.084,1.951) D22(-12.759,1.991) D23(-13.435,1.951) D24(-13.998,1.626) D25(-14.562,1.951) D26(-15.237,1.991) D27(-15.913,1.951) D28(-16.476,1.626) D29(-17.04,1.951) D30(-17.715,1.991) D31(-18.391,1.951) D32(-18.954,1.626) D33(-19.518,1.951) D34(-20.194,1.991) D36(-20.869,1.951) D37(-21.433,1.626) D38(-21.996,1.951) D39(-22.672,1.991) D40(-23.347,1.951) D41(-23.911,1.626) D42(-24.474,1.951) D44(-25.15,1.991) D45(-25.825,1.951) D46(-26.389,1.626) D47(-26.952,1.951) D48(-27.628,1.991) D50(-28.303,1.951) D51(-28.867,1.626) D52(-29.43,1.951) D53(-30.106,1.991) D54(-30.781,1.951) D55(-31.345,1.626) D56(-31.908,1.951) D58(-32.584,1.991) D59(-33.259,1.951) D60(-33.823,1.626) D61(-34.386,1.951) D62(-35.062,1.991) D63(-35.737,1.951) D64(-36.301,1.626) D65(-36.864,1.951) D66(-37.54,1.991) D67(-38.213,1.3) D68(-39.582,1.779) D69(-38.876,2.343) D71(-40.629,1.763) E1(0,2.274) E2(-0.65,2.274) E3(-1.3,2.274) E5(-2.66,2.723) E6(-3.575,2.723) E8(-4.489,2.723) E10(-5.403,2.723) E11(-6.318,2.723) E13(-7.232,2.723) E15(-8.147,2.723) E16(-9.061,2.723) E18(-9.975,2.723) E20(-10.89,2.723) E21(-11.804,2.723) E22(-12.719,2.723) E23(-13.633,2.723) E25(-14.547,2.723) E27(-15.462,2.723) E28(-16.376,2.723) E30(-17.291,2.723) E32(-18.205,2.723) E33(-19.119,2.723) E35(-20.034,2.723) E37(-20.948,2.723) E38(-21.863,2.723) E40(-22.777,2.723) E42(-23.691,2.723) E43(-24.606,2.723) E45(-25.52,2.723) E46(-26.435,2.723) E48(-27.349,2.723) E50(-28.263,2.723) E52(-29.178,2.723) E53(-30.092,2.723) E55(-31.007,2.723) E56(-31.921,2.723) E58(-32.835,2.723) E60(-33.75,2.723) E61(-34.664,2.723) E63(-35.629,2.659) E65(-36.645,2.659) E66(-37.661,2.659) E68(-38.213,1.951) F2(-0.975,2.848) F4(-1.951,2.848) F5(-2.66,3.373) F6(-3.575,3.373) F8(-4.489,3.373) F10(-5.403,3.373) F11(-6.318,3.373) F13(-7.232,3.373) F15(-8.147,3.373) F16(-9.061,3.373) F18(-9.975,3.373) F20(-10.89,3.373) F21(-11.804,3.373) F22(-12.719,3.373) F23(-13.633,3.373) F25(-14.547,3.373) F27(-15.462,3.373) F28(-16.376,3.373) F30(-17.291,3.373) F32(-18.205,3.373) F33(-19.119,3.373) F35(-20.034,3.373) F37(-20.948,3.373) F38(-21.863,3.373) F40(-22.777,3.373) F42(-23.691,3.373) F43(-24.606,3.373) F45(-25.52,3.373) F46(-26.435,3.373) F48(-27.349,3.373) F50(-28.263,3.373) F52(-29.178,3.373) F53(-30.092,3.373) F55(-31.007,3.373) F56(-31.921,3.373) F58(-32.835,3.373) F60(-33.75,3.373) F61(-34.664,3.373) F63(-35.629,3.31) F65(-36.645,3.31) F66(-37.661,3.31) F68(-38.876,2.994) G4(-1.951,3.511) G5(-2.66,4.023) G6(-3.575,4.023) G8(-4.489,4.023) G10(-5.403,4.023) G11(-6.318,4.023) G13(-7.232,4.023) G15(-8.147,4.023) G16(-9.061,4.023) G18(-9.975,4.023) G20(-10.89,4.023) G21(-11.804,4.023) G22(-12.719,4.023) G23(-13.633,4.023) G25(-14.547,4.023) G27(-15.462,4.023) G28(-16.376,4.023) G30(-17.291,4.023) G32(-18.205,4.023) G33(-19.119,4.023) G35(-20.034,4.023) G37(-20.948,4.023) G38(-21.863,4.023) G40(-22.777,4.023) G42(-23.691,4.023) G43(-24.606,4.023) G45(-25.52,4.023) G46(-26.435,4.023) G48(-27.349,4.023) G50(-28.263,4.023) G52(-29.178,4.023) G53(-30.092,4.023) G55(-31.007,4.023) G56(-31.921,4.023) G58(-32.835,4.023) G60(-33.75,4.023) G61(-34.664,4.023) G63(-35.629,3.96) G65(-36.645,3.96) G66(-37.661,3.96) G68(-38.678,3.655) G69(-39.328,3.655) H3(-1.626,4.174) H5(-2.66,4.674) H6(-3.575,4.674) H8(-4.489,4.674) H10(-5.403,4.674) H11(-6.318,4.674) H13(-7.232,4.674) H15(-8.147,4.674) H16(-9.061,4.674) H18(-9.975,4.674) H20(-10.89,4.674) H21(-11.804,4.674) H63(-35.629,4.61) H65(-36.645,4.61) H66(-37.661,4.61) H69(-39.003,4.218) J4(-1.951,4.837) J5(-2.66,5.324) J6(-3.575,5.324) J8(-4.489,5.324) J10(-5.403,5.324) J11(-6.318,5.324) J13(-7.232,5.324) J22(-13.176,4.488) J23(-14.09,4.488) J25(-15.005,4.488) J27(-15.919,4.488) J28(-16.833,4.488) J30(-17.748,4.488) J32(-18.662,4.488) J33(-19.577,4.488) J35(-20.491,4.488) J37(-21.405,4.488) J38(-22.32,4.488) J40(-23.234,4.488) J42(-24.149,4.488) J43(-25.063,4.488) J45(-25.977,4.488) J46(-26.892,4.488) J48(-27.806,4.488) J50(-28.721,4.488) J52(-29.635,4.488) J53(-30.549,4.488) J55(-31.464,4.488) J56(-32.378,4.488) J58(-33.293,4.488) J60(-34.207,4.488) J68(-38.676,4.794) K15(-8.126,5.438) K16(-8.776,5.438) K17(-9.426,5.438) K18(-10.077,5.438) K19(-10.727,5.438) K20(-11.377,5.438) K21(-12.027,5.438) K22(-12.719,4.952) K23(-13.633,4.952) K25(-14.547,4.952) K27(-15.462,4.952) K28(-16.376,4.952) K30(-17.291,4.952) K32(-18.205,4.952) K33(-19.119,4.952) K35(-20.034,4.952) K37(-20.948,4.952) K38(-21.863,4.952) K40(-22.777,4.952) K42(-23.691,4.952) K43(-24.606,4.952) K45(-25.52,4.952) K46(-26.435,4.952) K48(-27.349,4.952) K50(-28.263,4.952) K52(-29.178,4.952) K53(-30.092,4.952) K55(-31.007,4.952) K56(-31.921,4.952) K58(-32.835,4.952) K60(-33.75,4.952) K61(-34.664,4.952) K63(-35.447,5.26) K64(-36.097,5.26) K65(-36.747,5.26) K66(-37.398,5.26) K67(-38.048,5.26) K68(-38.666,5.468) K70(-39.653,5.57) L2(-0.975,5.5) L4(-1.951,5.5) L6(-2.729,5.974) L7(-3.379,5.974) L8(-4.029,5.974) L9(-4.679,5.974) L10(-5.33,5.974) L11(-5.98,5.974) L12(-6.63,5.974) L13(-7.28,5.974) L15(-8.126,6.276) L16(-8.776,6.276) L17(-9.426,6.276) L18(-10.077,6.276) L19(-10.727,6.276) L20(-11.377,6.276) L21(-12.027,6.276) L62(-34.958,5.689) L63(-35.427,6.147) L64(-36.077,6.147) L65(-36.727,6.147) L66(-37.377,6.147) L67(-38.028,6.147) L68(-38.678,6.147) L69(-39.328,6.147) L70(-39.978,6.147) L71(-40.629,6.147) M4(-1.951,6.163) M62(-34.958,6.604) N3(-1.626,6.826) N6(-2.729,6.914) N7(-3.379,6.914) N8(-4.029,6.914) N9(-4.679,6.914) N10(-5.33,6.914) N11(-5.98,6.914) N12(-6.63,6.914) N13(-7.28,6.914) N15(-8.126,7.114) N16(-8.776,7.114) N17(-9.426,7.114) N18(-10.077,7.114) N19(-10.727,7.114) N20(-11.377,7.114) N21(-12.027,7.114) N63(-35.427,7.061) N64(-36.077,7.061) N65(-36.727,7.061) N66(-37.377,7.061) N67(-38.028,7.061) N68(-38.678,7.061) N69(-39.328,7.061) N70(-39.978,7.061) N71(-40.629,7.061) P4(-1.951,7.489) P15(-8.126,7.952) P16(-8.776,7.952) P17(-9.426,7.952) P18(-10.077,7.952) P19(-10.727,7.952) P20(-11.377,7.952) P21(-12.027,7.952) P62(-34.958,7.518) R6(-2.729,7.981) R7(-3.379,7.981) R8(-4.029,7.981) R9(-4.679,7.981) R10(-5.33,7.981) R11(-5.98,7.981) R12(-6.63,7.981) R13(-7.28,7.981) R63(-35.427,7.975) R64(-36.077,7.975) R65(-36.727,7.975) R66(-37.377,7.975) R67(-38.028,7.975) R68(-38.678,7.975) R69(-39.328,7.975) R70(-39.978,7.975) R71(-40.629,7.975) T2(-0.975,8.152) T4(-1.951,8.152) T15(-8.126,8.791) T16(-8.776,8.791) T17(-9.426,8.791) T18(-10.077,8.791) T19(-10.727,8.791) T20(-11.377,8.791) T21(-12.027,8.791) T62(-34.958,8.433) U4(-1.951,8.815) U6(-2.729,9.047) U7(-3.379,9.047) U8(-4.029,9.047) U9(-4.679,9.047) U10(-5.33,9.047) U11(-5.98,9.047) U12(-6.63,9.047) U13(-7.28,9.047) U63(-35.427,8.89) U64(-36.077,8.89) U65(-36.727,8.89) U66(-37.377,8.89) U67(-38.028,8.89) U68(-38.678,8.89) U69(-39.328,8.89) U70(-39.978,8.89) U71(-40.629,8.89) V3(-1.626,9.478) V15(-8.126,9.629) V16(-8.776,9.629) V17(-9.426,9.629) V18(-10.077,9.629) V19(-10.727,9.629) V20(-11.377,9.629) V21(-12.027,9.629) V62(-34.958,9.347) W4(-1.951,10.141) W6(-2.729,10.114) W7(-3.379,10.114) W8(-4.029,10.114) W9(-4.679,10.114) W10(-5.33,10.114) W11(-5.98,10.114) W12(-6.63,10.114) W13(-7.28,10.114) W63(-35.427,9.804) W64(-36.077,9.804) W65(-36.727,9.804) W66(-37.377,9.804) W67(-38.028,9.804) W68(-38.678,9.804) W69(-39.328,9.804) W70(-39.978,9.804) W71(-40.629,9.804) Y15(-8.126,10.467) Y16(-8.776,10.467) Y17(-9.426,10.467) Y18(-10.077,10.467) Y19(-10.727,10.467) Y20(-11.377,10.467) Y21(-12.027,10.467) Y62(-34.958,10.261)
  oval 0.254x0.343 smd: A6(-2.847,0.325) A7(-3.523,0) A9(-4.65,0) A10(-5.325,0.325) A11(-6.001,0) A13(-7.128,0) A14(-7.803,0.325) A15(-8.479,0) A17(-9.606,0) A18(-10.281,0.325) A19(-10.957,0) A21(-12.084,0) A22(-12.759,0.325) A23(-13.435,0) A25(-14.562,0) A26(-15.237,0.325) A27(-15.913,0) A29(-17.04,0) A30(-17.715,0.325) A31(-18.391,0) A33(-19.518,0) A34(-20.194,0.325) A36(-20.869,0) A38(-21.996,0) A39(-22.672,0.325) A40(-23.347,0) A42(-24.474,0) A44(-25.15,0.325) A45(-25.825,0) A47(-26.952,0) A48(-27.628,0.325) A50(-28.303,0) A52(-29.43,0) A53(-30.106,0.325) A54(-30.781,0) A56(-31.908,0) A58(-32.584,0.325) A59(-33.259,0) A61(-34.386,0) A62(-35.062,0.325) A63(-35.737,0) A65(-36.864,0) A66(-37.54,0.325) A67(-38.215,0) AY7(-3.763,21.328) AY9(-4.898,21.328) AY11(-6.184,21.328) AY13(-7.319,21.328) AY15(-8.604,21.328) AY17(-9.74,21.328) AY20(-11.025,21.328) AY22(-12.16,21.328) AY25(-13.486,21.328) AY31(-17.167,21.328) AY33(-18.467,21.328) AY39(-22.148,21.328) AY42(-23.423,21.328) AY48(-27.103,21.328) AY50(-28.236,21.328) AY56(-31.916,21.328) AY59(-33.191,21.328) AY65(-36.872,21.328) AY67(-38.216,21.328) B7(-3.523,0.65) B9(-4.65,0.65) B11(-6.001,0.65) B13(-7.128,0.65) B15(-8.479,0.65) B17(-9.606,0.65) B19(-10.957,0.65) B21(-12.084,0.65) B23(-13.435,0.65) B25(-14.562,0.65) B27(-15.913,0.65) B29(-17.04,0.65) B31(-18.391,0.65) B33(-19.518,0.65) B36(-20.869,0.65) B38(-21.996,0.65) B40(-23.347,0.65) B42(-24.474,0.65) B45(-25.825,0.65) B47(-26.952,0.65) B50(-28.303,0.65) B52(-29.43,0.65) B54(-30.781,0.65) B56(-31.908,0.65) B59(-33.259,0.65) B61(-34.386,0.65) B63(-35.737,0.65) B65(-36.864,0.65) B67(-38.215,0.65) BA4(-1.948,22.004) BA6(-3.141,21.572) BA7(-3.705,21.978) BA9(-4.898,21.978) BA10(-5.561,21.572) BA11(-6.125,21.978) BA13(-7.319,21.978) BA14(-7.982,21.572) BA15(-8.546,21.978) BA17(-9.74,21.978) BA18(-10.403,21.572) BA20(-10.966,21.978) BA22(-12.16,21.978) BA25(-13.486,21.978) BA26(-14.149,21.653) BA27(-14.812,21.978) BA29(-15.841,21.978) BA30(-16.504,21.653) BA31(-17.167,21.978) BA33(-18.467,21.978) BA34(-19.13,21.653) BA35(-19.793,21.978) BA37(-20.822,21.978) BA38(-21.485,21.653) BA39(-22.148,21.978) BA42(-23.423,21.978) BA43(-24.086,21.653) BA44(-24.748,21.978) BA46(-25.777,21.978) BA47(-26.44,21.653) BA48(-27.103,21.978) BA50(-28.236,21.978) BA51(-28.899,21.653) BA52(-29.562,21.978) BA54(-30.59,21.978) BA55(-31.253,21.653) BA56(-31.916,21.978) BA59(-33.191,21.978) BA60(-33.854,21.653) BA61(-34.517,21.978) BA63(-35.546,21.978) BA64(-36.209,21.653) BA65(-36.872,21.978) BA66(-37.535,21.653) BA67(-38.216,21.978) BB5(-2.529,22.628) BB6(-3.141,22.303) BB7(-3.705,22.628) BB9(-4.898,22.628) BB10(-5.561,22.303) BB11(-6.125,22.628) BB13(-7.319,22.628) BB14(-7.982,22.303) BB15(-8.546,22.628) BB17(-9.74,22.628) BB18(-10.403,22.303) BB20(-10.966,22.628) BB22(-12.16,22.628) BB23(-12.849,22.222) BB25(-13.486,22.628) BB26(-14.149,22.303) BB27(-14.812,22.628) BB29(-15.841,22.628) BB30(-16.504,22.303) BB31(-17.167,22.628) BB32(-17.83,22.222) BB33(-18.467,22.628) BB34(-19.13,22.303) BB35(-19.793,22.628) BB37(-20.822,22.628) BB38(-21.485,22.303) BB39(-22.148,22.628) BB41(-22.785,22.222) BB42(-23.423,22.628) BB43(-24.086,22.303) BB44(-24.748,22.628) BB46(-25.777,22.628) BB47(-26.44,22.303) BB48(-27.103,22.628) BB50(-28.236,22.628) BB51(-28.899,22.303) BB52(-29.562,22.628) BB54(-30.59,22.628) BB55(-31.253,22.303) BB56(-31.916,22.628) BB57(-32.554,22.222) BB59(-33.191,22.628) BB60(-33.854,22.303) BB61(-34.517,22.628) BB63(-35.546,22.628) BB64(-36.209,22.303) BB65(-36.872,22.628) BB66(-37.535,22.303) BB67(-38.216,22.628)
  oval 0.343x0.254 smd: AA1(-0.325,10.804) AB1(0,11.467) AB2(-0.65,11.467) AB3(-1.3,11.467) AC1(-0.325,12.13) AC2(-0.975,12.13) AD1(0,12.792) AD2(-0.65,12.792) AD3(-1.3,12.792) AF1(-0.325,13.455) AF70(-39.978,13.154) AF71(-40.629,13.154) AG1(0,14.118) AG2(-0.65,14.118) AG3(-1.3,14.118) AG70(-39.653,13.817) AG71(-40.303,13.817) AH1(-0.325,14.781) AH2(-0.975,14.781) AH68(-38.678,14.48) AH69(-39.328,14.48) AH70(-39.978,14.48) AH71(-40.629,14.48) AJ1(0,15.444) AJ2(-0.65,15.444) AJ3(-1.3,15.444) AK70(-40.303,15.143) AL1(-0.325,16.107) AL68(-38.678,15.806) AL69(-39.328,15.806) AL70(-39.978,15.806) AL71(-40.629,15.806) AM1(0,16.77) AM2(-0.65,16.77) AM3(-1.3,16.77) AM70(-39.653,16.469) AM71(-40.303,16.469) AN1(-0.325,17.433) AN2(-0.975,17.433) AN70(-39.978,17.132) AN71(-40.629,17.132) AP1(0,18.096) AP2(-0.65,18.096) AP3(-1.3,18.096) AR70(-39.978,18.16) AR71(-40.629,18.16) AT1(-0.325,18.759) AT70(-39.653,18.823) AT71(-40.303,18.823) AU1(0,19.422) AU2(-0.65,19.422) AU3(-1.3,19.422) AU68(-38.678,19.461) AU69(-39.328,19.486) AU70(-39.978,19.486) AU71(-40.629,19.486) AV1(0,20.142) AV2(-0.95,20.113) AV71(-40.629,20.215) AW2(-0.625,20.677) AW3(-1.275,20.677) E70(-39.978,2.305) E71(-40.629,2.413) F1(-0.325,2.848) F70(-39.526,2.994) F71(-40.176,2.931) G1(0,3.511) G2(-0.65,3.511) G3(-1.3,3.511) G70(-39.978,3.555) G71(-40.629,3.555) H1(-0.325,4.174) H2(-0.975,4.174) H70(-39.653,4.218) H71(-40.303,4.218) J1(0,4.837) J2(-0.65,4.837) J3(-1.3,4.837) J69(-39.328,4.881) J70(-39.978,4.881) J71(-40.629,4.881) K71(-40.303,5.57) L1(-0.325,5.5) M1(0,6.163) M2(-0.65,6.163) M3(-1.3,6.163) N1(-0.325,6.826) N2(-0.975,6.826) P1(0,7.489) P2(-0.65,7.489) P3(-1.3,7.489) T1(-0.325,8.152) U1(0,8.815) U2(-0.65,8.815) U3(-1.3,8.815) V1(-0.325,9.478) V2(-0.975,9.478) W1(0,10.141) W2(-0.65,10.141) W3(-1.3,10.141)
